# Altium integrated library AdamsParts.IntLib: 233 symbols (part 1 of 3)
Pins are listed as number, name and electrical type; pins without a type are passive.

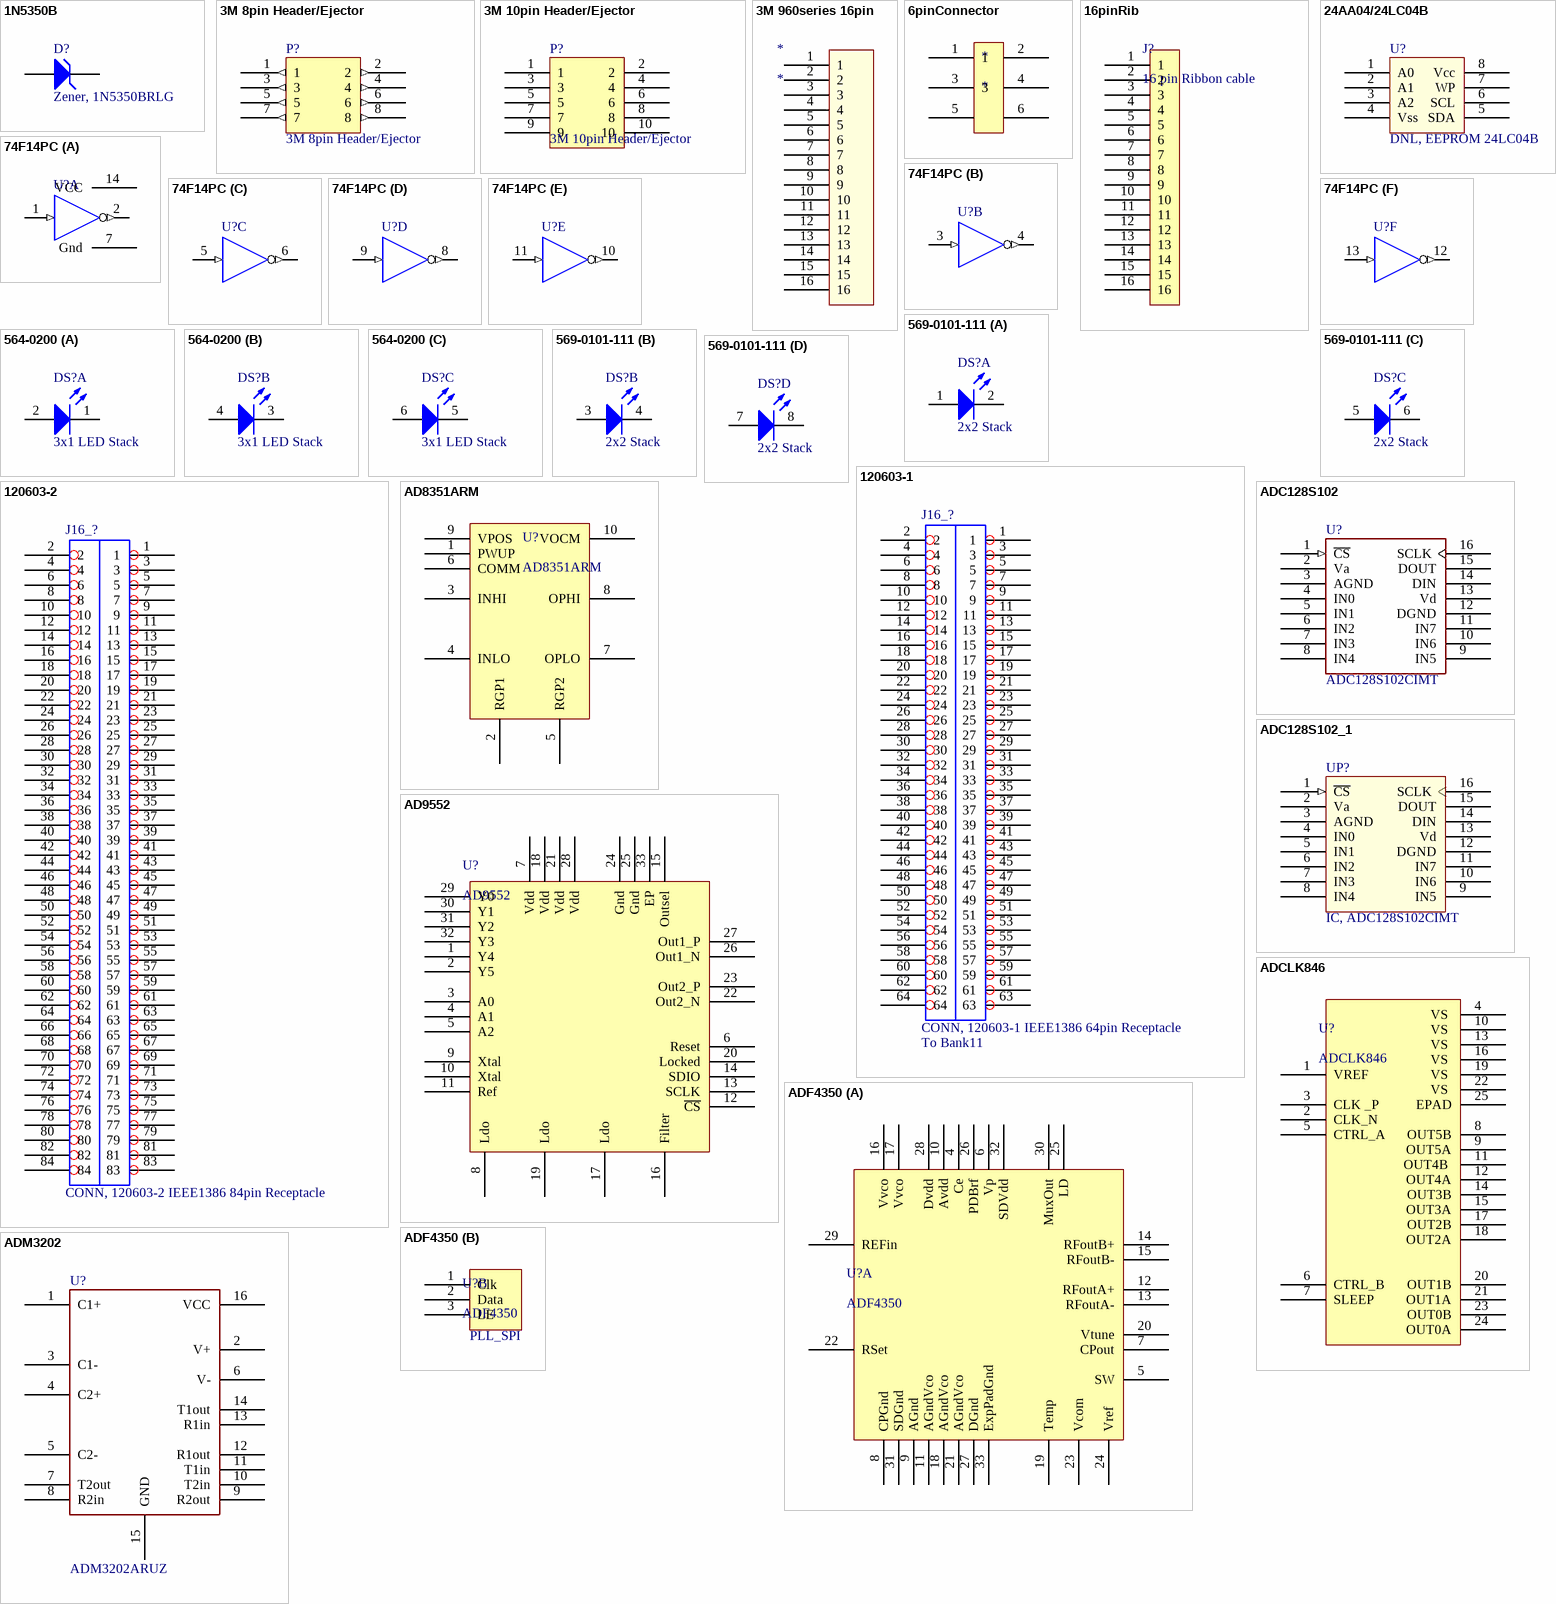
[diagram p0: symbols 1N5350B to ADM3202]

## 1N5350B
designator D?, comment Zener, 1N5350BRLG
Zener Diode, 13V, 5W
footprint A-500 (Diode, Axial; Body 8.9 x 3.7 mm (LxDia. max), Lead Dia. 1.09 mm (max))
simulation model 1N5350B (DIODE)
signal-integrity model 1N5350B
pins: 1 A, 2 K

## 3M 8pin Header/Ejector
designator P?
footprint 3M 8pin latch/ejector
pins: 1 (out), 2 (out), 3 (out), 4 (out), 5 (out), 6 (out), 7 (out), 8 (out)

## 3M 10pin Header/Ejector
designator P?
footprint 3M 10pin latch/ejector
pins: 1, 2, 3, 4, 5, 6, 7, 8, 9, 10

## 3M 960series 16pin
designator *
footprint 3M 960series 16pin
pins: 1, 2, 3, 4, 5, 6, 7, 8, 9, 10, 11, 12, 13, 14, 15, 16

## 6pinConnector
designator *
footprint Tyco 6pin Shrouded Header
pins: 1, 2, 3, 4, 5, 6

## 16pinRib
designator J?, comment 16 pin Ribbon cable
footprint 16pinRib (16 pin ribbon connector)
pins: 1, 2, 3, 4, 5, 6, 7, 8, 9, 10, 11, 12, 13, 14, 15, 16

## 24AA04/24LC04B
designator U?, comment DNL, EEPROM 24LC04B
4K I2C Serial EEPROM
footprint TSSOP8-4.4 (8-Lead Plastic TSSOP 4.4mm)
pins: 1 A0, 2 A1, 3 A2, 4 Vss (power), 5 SDA, 6 SCL, 7 WP, 8 Vcc (power)

## 74F14PC
designator U?
Hex Inverter Schmitt-Trigger, 14-Pin PDIP, Commercial Grade; IC_Technology: F
footprint N14A (DIP, 14-Leads, Row Spacing 7.62mm, Pitch 2.54mm, Body 19.18x6.35mm)
3D model N14A (DIP, 14-Pin, Row Spacing 7.62 mm, Pitch 2.54 mm)
simulation model FSC_74F14 (SIMCODE)
signal-integrity model 74F14PC
part A pins: 1 I (in), 2 ~{O} (out), 7 Gnd, 14 VCC
part B pins: 3 I (in), 4 ~{O} (out)
part C pins: 5 I (in), 6 ~{O} (out)
part D pins: 8 ~{O} (out), 9 I (in)
part E pins: 10 ~{O} (out), 11 I (in)
part F pins: 12 ~{O} (out), 13 I (in)

## 564-0200
designator DS?, comment 3x1 LED Stack
Color: Green (x 3); Configuration: 3 high x 1 wide; Voltage Rating: 2.0V; Current: 20mA; Lens Style/Size: Round, 3mm, T-1; Lens Type: Diffused, Red Tinted
footprint LED3x1
part A pins: 1 K1, 2 A1
part B pins: 3 K2, 4 A2
part C pins: 5 K3, 6 A3

## 569-0101-111
designator DS?, comment 2x2 Stack
LED 2X2 3MM HI DENSITY RED PCMNT; Color: Red (x 4); Configuration: 2 high x 2 wide; Voltage Rating: 2.0V; Current: 20mA; Lens Style/Size: Round, 3mm, T-1; Lens Type: Diffused, Red Tinted
footprint LED2x2 (LED 2x2 Stack from Dialight)
part A pins: 1 A1, 2 K1
part B pins: 3 A2, 4 K2
part C pins: 5 A3, 6 K3
part D pins: 7 A4, 8 K4

## 120603-1
designator J16_?, comment CONN, 120603-1 IEEE1386 64pin Receptacle  Relation: To Bank11
1.0mm FH (IEEE1386) 64-pin Connector
footprint 120603-1
pins: 1, 2, 3, 4, 5, 6, 7, 8, 9, 10, 11, 12, 13, 14, 15, 16, 17, 18, 19, 20, 21, 22, 23, 24, 25, 26, 27, 28, 29, 30, 31, 32, 33, 34, 35, 36, 37, 38, 39, 40, 41, 42, 43, 44, 45, 46, 47, 48, 49, 50, 51, 52, 53, 54, 55, 56, 57, 58, 59, 60, 61, 62, 63, 64

## 120603-2
designator J16_?, comment CONN, 120603-2 IEEE1386 84pin Receptacle
1.0mm FH (IEEE1386) 84-pin Connector
footprint 120603-2 (1.0mm FH (IEEE1386) 84-Pin Connector)
pins: 1, 2, 3, 4, 5, 6, 7, 8, 9, 10, 11, 12, 13, 14, 15, 16, 17, 18, 19, 20, 21, 22, 23, 24, 25, 26, 27, 28, 29, 30, 31, 32, 33, 34, 35, 36, 37, 38, 39, 40, 41, 42, 43, 44, 45, 46, 47, 48, 49, 50, 51, 52, 53, 54, 55, 56, 57, 58, 59, 60, 61, 62, 63, 64, 65, 66, 67, 68, 69, 70, 71, 72, 73, 74, 75, 76, 77, 78, 79, 80, 81, 82, 83, 84

## AD8351ARM
designator U?
footprint MSOP-UN10_N (TSSOP, 10-Leads, Body 3x3mm, Pitch 0.5mm, IPC Medium Density)
pins: 1 PWUP, 2 RGP1, 3 INHI, 4 INLO, 5 RGP2, 6 COMM, 7 OPLO, 8 OPHI, 9 VPOS, 10 VOCM

## AD9552
designator U?
PLL
footprint QFN50P500X475X100-32N (QFN, 32-Leads, Body 4.8x5.0mm (max), Pitch 0.50mm, IPC Medium Density)
pins: 1 Y4, 2 Y5, 3 A0, 4 A1, 5 A2, 6 Reset, 7 Vdd, 8 Ldo, 9 Xtal, 10 Xtal, 11 Ref, 12 ~{CS}, 13 SCLK, 14 SDIO, 15 Outsel, 16 Filter, 17 Ldo, 18 Vdd, 19 Ldo, 20 Locked, 21 Vdd, 22 Out2_N, 23 Out2_P, 24 Gnd, 25 Gnd, 26 Out1_N, 27 Out1_P, 28 Vdd, 29 Y0, 30 Y1, 31 Y2, 32 Y3, 33 EP

## ADC128S102
designator U?, comment ADC128S102CIMT
ADC, 8-Channels, 500kSPS to 1 MSPS, 12-Bit; Manufacturer: National Semiconductor; Manufacturers P/N: ADC128S102CIMT/NOPB
footprint TSSOP-16
pins: 1 ~{CS} (in), 2 Va (power), 3 AGND (power), 4 IN0, 5 IN1, 6 IN2, 7 IN3, 8 IN4, 9 IN5, 10 IN6, 11 IN7, 12 DGND (power), 13 Vd (power), 14 DIN, 15 DOUT, 16 SCLK

## ADC128S102_1
designator UP?, comment IC, ADC128S102CIMT
8-Channels, 500kSPS to 1 MSPS, 12-Bit ADC
footprint SSO-G16/X.45 (SSOP; 16 Leads; Body Width 5.3 mm; Pitch 0.65 mm)
pins: 1 ~{CS} (in), 2 Va (power), 3 AGND (power), 4 IN0, 5 IN1, 6 IN2, 7 IN3, 8 IN4, 9 IN5, 10 IN6, 11 IN7, 12 DGND (power), 13 Vd (power), 14 DIN, 15 DOUT, 16 SCLK

## ADCLK846
designator U?
Clock fanout buffer
footprint QFN50P400X375X100-24N (QFN, 24-Leads, Body 3.8x4.0mm (max), Pitch 0.50mm, IPC Medium Density)
pins: 1 VREF , 2 CLK_N, 3 CLK _P, 4 VS , 5 CTRL_A , 6 CTRL_B , 7 SLEEP , 8 OUT5B, 9 OUT5A, 10 VS , 11 OUT4B , 12 OUT4A, 13 VS , 14 OUT3B, 15 OUT3A, 16 VS , 17 OUT2B, 18 OUT2A, 19 VS , 20 OUT1B, 21 OUT1A, 22 VS , 23 OUT0B, 24 OUT0A, 25 EPAD

## ADF4350
designator U?
footprint QFN50P500X475X100-32M (QFN, 32-Leads, Body 4.8x5.0mm (max), Pitch 0.50mm, IPC Low Density)
part A pins: 4 Ce, 5 SW, 6 Vp, 7 CPout, 8 CPGnd, 9 AGnd, 10 Avdd, 11 AGndVco, 12 RFoutA+, 13 RFoutA-, 14 RFoutB+, 15 RFoutB-, 16 Vvco, 17 Vvco, 18 AGndVco, 19 Temp, 20 Vtune, 21 AGndVco, 22 RSet, 23 Vcom, 24 Vref, 25 LD, 26 PDBrf, 27 DGnd, 28 Dvdd, 29 REFin, 30 MuxOut, 31 SDGnd, 32 SDVdd, 33 ExpPadGnd
part B pins: 1 Clk, 2 Data, 3 LE

## ADM3202
designator U?, comment ADM3202ARUZ
Transceiver, Dual RS232; Manufacturer: Analog Devices Inc
footprint TSSOP-16
pins: 1 C1+, 2 V+ (power), 3 C1-, 4 C2+, 5 C2-, 6 V- (power), 7 T2out, 8 R2in, 9 R2out, 10 T2in, 11 T1in, 12 R1out, 13 R1in, 14 T1out, 15 GND (power), 16 VCC (power)

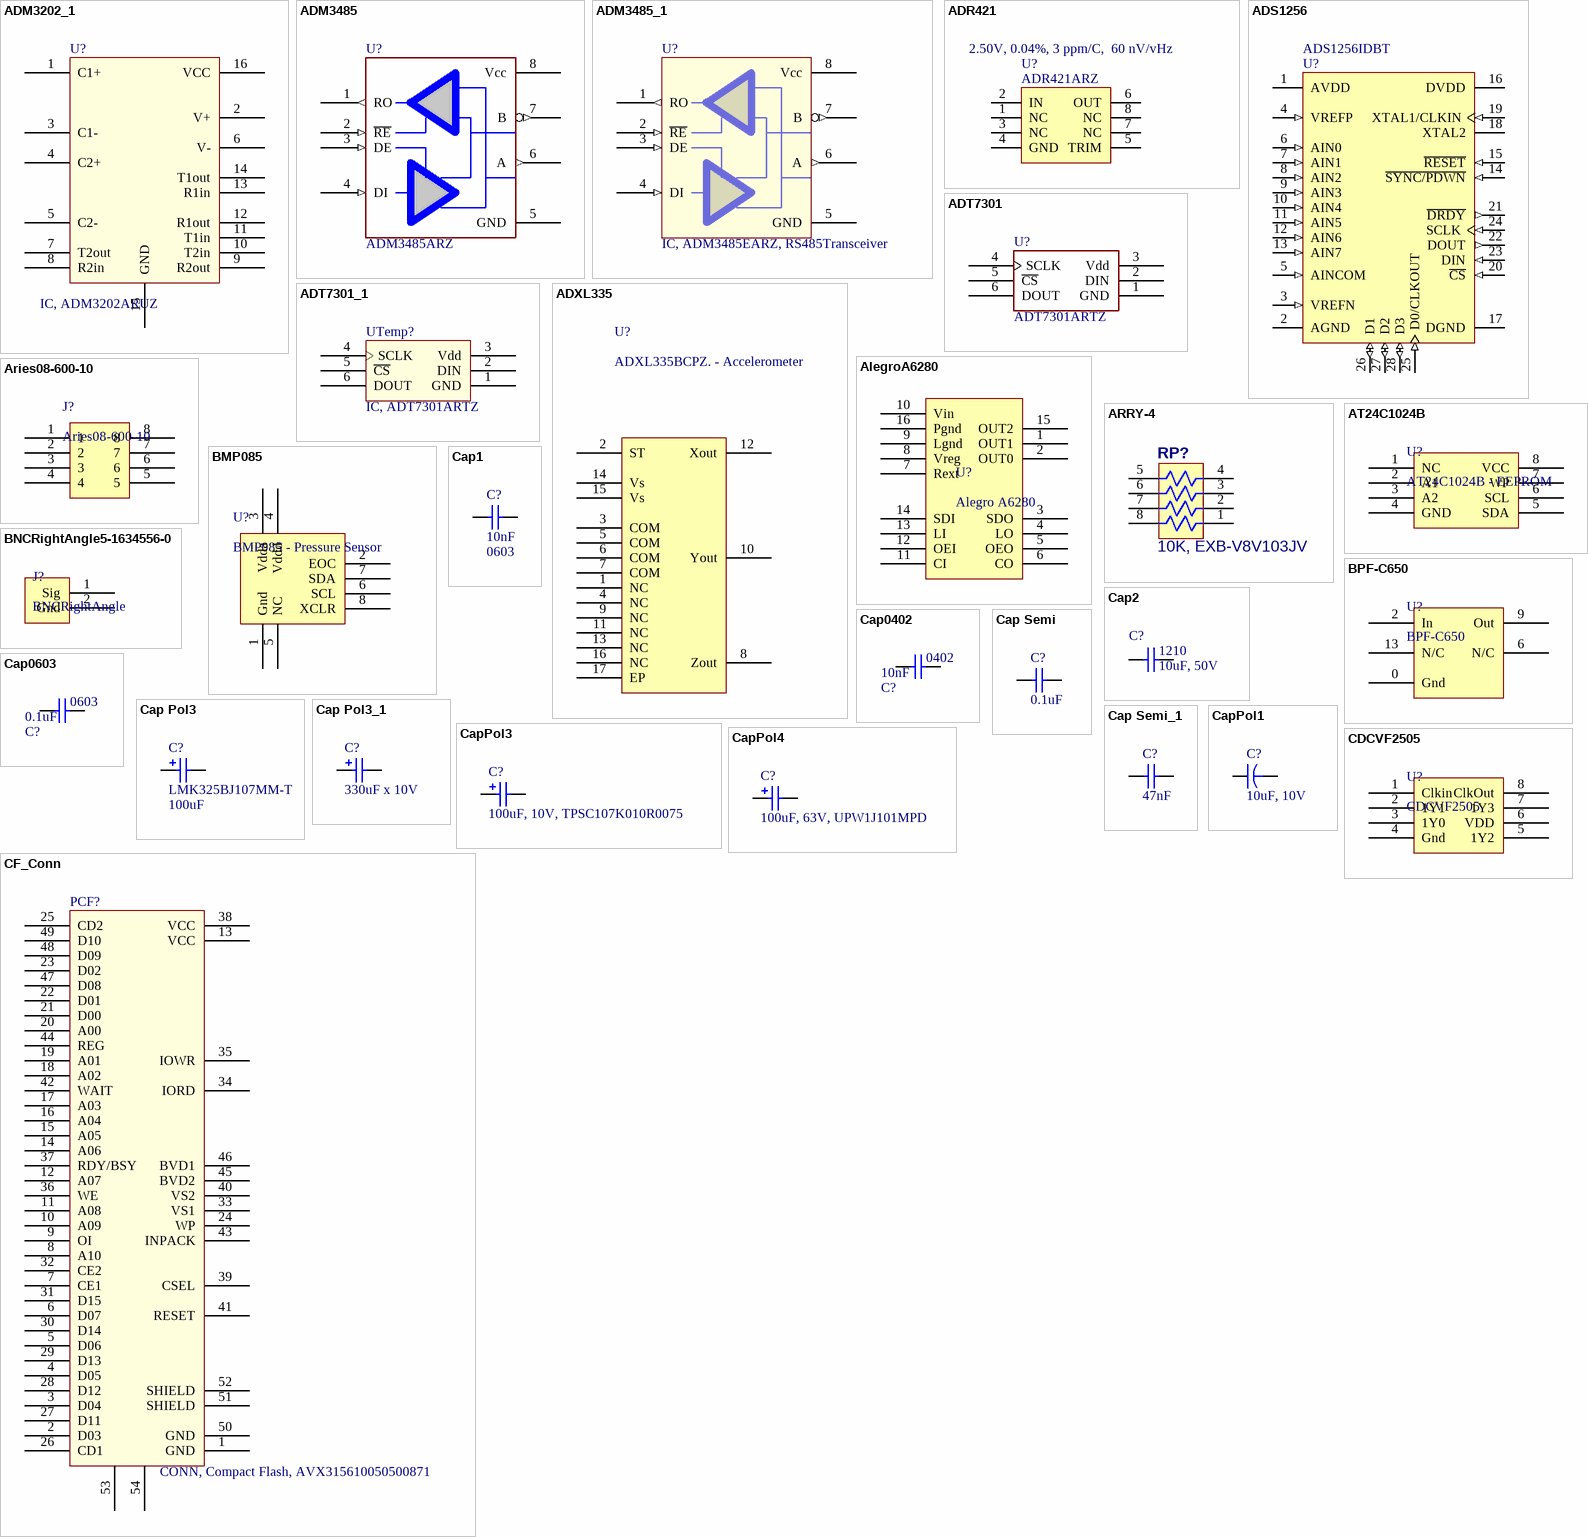
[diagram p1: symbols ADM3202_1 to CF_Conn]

## ADM3202_1
designator U?, comment IC, ADM3202ARUZ
Line Drivers/Receivers
footprint SSO-G16/X.45 (SSOP; 16 Leads; Body Width 5.3 mm; Pitch 0.65 mm)
pins: 1 C1+, 2 V+ (power), 3 C1-, 4 C2+, 5 C2-, 6 V- (power), 7 T2out, 8 R2in, 9 R2out, 10 T2in, 11 T1in, 12 R1out, 13 R1in, 14 T1out, 15 GND (power), 16 VCC (power)

## ADM3485
designator U?, comment ADM3485ARZ
Transceiver, 20 Mbps, EIA RS-485; Manufacturer: Analog Devices Inc
footprint SO8
pins: 1 RO (out), 2 ~{RE} (in), 3 DE (in), 4 DI (in), 5 GND (power), 6 A (out), 7 B (out), 8 Vcc (power)

## ADM3485_1
designator U?, comment IC, ADM3485EARZ, RS485Transceiver
20 Mbps, EIA RS-485 Transceiver
footprint SO-G8/Y1.9 (Small Outline; 8 Leads; Body Width 3.9 mm; Pitch 1.27 mm)
pins: 1 RO (out), 2 ~{RE} (in), 3 DE (in), 4 DI (in), 5 GND (power), 6 A (out), 7 B (out), 8 Vcc (power)

## ADR421
designator U?, comment ADR421ARZ  Param: 2.50V, 0.04%, 3 ppm/C,  60 nV/vHz
Voltage Reference, 2.50V, 0.04%; Manufacturer: Analog Devices Inc
footprint SO8
pins: 1 NC, 2 IN (power), 3 NC, 4 GND (power), 5 TRIM, 6 OUT (power), 7 NC, 8 NC

## ADS1256
designator U?, comment ADS1256IDBT
ADC 24-Bit; Manufacturer: Texas Instruments
footprint SSOP-28
pins: 1 AVDD (power), 2 AGND (power), 3 VREFN (in), 4 VREFP (in), 5 AINCOM (in), 6 AIN0 (in), 7 AIN1 (in), 8 AIN2 (in), 9 AIN3 (in), 10 AIN4 (in), 11 AIN5 (in), 12 AIN6 (in), 13 AIN7 (in), 14 ~{SYNC/PDWN} (in), 15 ~{RESET} (in), 16 DVDD (power), 17 DGND (power), 18 XTAL2, 19 XTAL1/CLKIN (in), 20 ~{CS} (in), 21 ~{DRDY} (out), 22 DOUT (out), 23 DIN (in), 24 SCLK (in), 25 D0/CLKOUT (in), 26 D1 (io), 27 D2 (io), 28 D3 (io)

## ADT7301
designator U?, comment ADT7301ARTZ
Digital Temperature Sensor, 13-Bit, +/-1 Degree Accurate; Manufacturer: Analog Devices Inc
footprint SOT23-6 (SOT-23/SC-74A; 5 Leads; Body 3.1 x 3 mm, inc. leads (LxW max))
pins: 1 GND (power), 2 DIN, 3 Vdd (power), 4 SCLK, 5 ~{CS}, 6 DOUT

## ADT7301_1
designator UTemp?, comment IC, ADT7301ARTZ
Digital Temperature Sensor, 13-Bit, +/-1 Degree Accurate
footprint SO-G6/E2.4 (Small Outline; 6 Leads; Body 3.6 x 3.6 mm, inc. leads (LxW max))
pins: 1 GND (power), 2 DIN, 3 Vdd (power), 4 SCLK, 5 ~{CS}, 6 DOUT

## ADXL335
designator U?, comment ADXL335BCPZ. - Accelerometer
footprint ADXL335 (QFN, 16-Leads, Body 4.2x4.2mm (max), Pitch 0.65mm, IPC Low Density)
pins: 1 NC, 2 ST, 3 COM, 4 NC, 5 COM, 6 COM, 7 COM, 8 Zout, 9 NC, 10 Yout, 11 NC, 12 Xout, 13 NC, 14 Vs, 15 Vs, 16 NC, 17 EP

## AlegroA6280
designator U?, comment Alegro A6280
footprint DIP16
pins: 1 OUT1, 2 OUT0, 3 SDO, 4 LO, 5 OEO, 6 CO, 7 Rext, 8 Vreg, 9 Lgnd, 10 Vin, 11 CI, 12 OEI, 13 LI, 14 SDI, 15 OUT2, 16 Pgnd

## Aries08-600-10
designator J?
Aries08-600-10 - Dip 8 header
footprint Aries08-600-10 (8 PIN DIP HEADER)
pins: 1, 2, 3, 4, 5, 6, 7, 8

## ARRY-4
designator RP?, comment 10K, EXB-V8V103JV
4x 0603 RES ARRAY 10K OHM 5% SMD; Part Field 1: Chip Resistor Array in 3.2 x 1.6 Concave package; Manufacturer: Panasonic - ECG
footprint EXB-V8V
pins: 1 R1A, 2 R2A, 3 R3A, 4 R4A, 5 R4B, 6 R3B, 7 R2B, 8 R1B

## AT24C1024B
designator U?, comment AT24C1024B - EEPROM
footprint SO8/L200
pins: 1 NC, 2 A1, 3 A2, 4 GND, 5 SDA, 6 SCL, 7 WP, 8 VCC

## BMP085
designator U?, comment BMP085 - Pressure Sensor
footprint BMP085 (Pressure sensor)
pins: 1 Gnd, 2 EOC, 3 Vdda, 4 Vddd, 5 NC, 6 SCL, 7 SDA, 8 XCLR

## BNCRightAngle5-1634556-0
designator J?, comment BNCRightAngle
footprint BNCRightAngle5-1634556-0
pins: 1 Sig, 2 Gnd

## BPF-C650
designator U?
footprint HU1186
pins: 0 Gnd, 2 In, 6 N/C, 9 Out, 13 N/C

## Cap1
designator C?, comment 10nF  Footprint: 0603
CAP 10000PF 5% 50V CERAMIC X7R 0603 (or Equivalent); Manufacturer: Kemet; Manufacturers P/N: C0603C103J5RACTU
simulation model CAP (Capacitor)
signal-integrity model Cap
footprint 0603
pins: 1, 2

## Cap2
designator C?, comment 10uF, 50V  Footprint: 1210
CAP CER 10UF, 50V, 10%, UMK325BJ106KM-T; Manufacturer: Taiyo Yuden; Param: 50V, X5R, 10%
simulation model CAP (Capacitor)
signal-integrity model Cap
footprint 1210
pins: 1, 2

## Cap0402
designator C?, comment 10nF  Footprint: 0402
Capacitor, Ceramic, 0402
simulation model CAP (Capacitor)
signal-integrity model Cap
pins: 1, 2

## Cap0603
designator C?, comment 0.1uF  Footprint: 0603
Capacitor, Ceramic, 0603
simulation model CAP (Capacitor)
signal-integrity model Cap
footprint 0603
footprint 0805
pins: 1, 2

## Cap Pol3
designator C?, comment LMK325BJ107MM-T  value 100uF
CAP CER 100UF 10V X5R 1210 20%; Manufacturer: Taiyo Yuden
simulation model CAP (Capacitor)
signal-integrity model Cap Pol
footprint 1210 (Chip Capacitor; Body 3.2 x 2.5 mm (LxW typ))
pins: 1, 2
1 alternate drawing of the same symbol

## Cap Pol3_1
designator C?, comment 330uF x 10V
CAP TANTD TPSD337K010R0100
footprint CC2012-0805 (Chip Capacitor; Body 2.0 x 1.2 mm (LxW typ))
footprint CC4532-1812 (Chip Capacitor; Body 4.5 x 3.2 mm (LxW typ))
footprint CC4564-1825 (Chip Capacitor; Body 4.5 x 6.4 mm (LxW typ))
footprint CC5664-2225 (Chip Capacitor; Body 5.6 x 6.4 mm (LxW typ))
footprint CC5750-2220 (Chip Capacitor; Body 5.7 x 5.0 mm (LxW typ))
simulation model CAP (Capacitor)
signal-integrity model Cap Pol
footprint CC7343-31_Dsize
pins: 1, 2
1 alternate drawing of the same symbol

## Cap Semi
designator C?, comment 0.1uF
CAP .10UF 5% 16V CERAMIC X7R 0603 (or Equivalent); Manufacturer: Kemet; Manufacturers P/N: C0603C104J4RACTU
footprint CC3216-1206 (Chip Capacitor; Body 3.2 x 1.6 mm (LxW typ))
footprint CC1005-0402 (Chip Capacitor; Body 1.0 x 0.5 mm (LxW typ))
footprint CC1310-0504 (Chip Capacitor; Body 1.2 x 1.0 mm (LxW typ))
footprint CC1608-0603 (Chip Capacitor; Body 1.6 x 0.8 mm (LxW typ))
footprint CC3225-1210 (Chip Capacitor; Body 3.2 x 2.5 mm (LxW typ))
simulation model CAP (Semiconductor Capacitor)
signal-integrity model Cap Semi
pins: 1, 2

## Cap Semi_1
designator C?, comment 47nF
Capacitor (Semiconductor SIM Model)
footprint CC3216-1206 (Chip Capacitor; Body 3.2 x 1.6 mm (LxW typ))
footprint CC1005-0402 (Chip Capacitor; Body 1.0 x 0.5 mm (LxW typ))
footprint CC1310-0504 (Chip Capacitor; Body 1.2 x 1.0 mm (LxW typ))
footprint CC1608-0603 (Chip Capacitor; Body 1.6 x 0.8 mm (LxW typ))
footprint CC3225-1210 (Chip Capacitor; Body 3.2 x 2.5 mm (LxW typ))
simulation model CAP (Semiconductor Capacitor)
signal-integrity model Cap Semi
pins: 1, 2

## CapPol1
designator C?, comment 10uF, 10V
CAP CER 10V, X5R, 10%, LMK212BJ106KG-T; Manufacturer: Taiyo Yuden
simulation model CAP (Capacitor)
signal-integrity model Cap
footprint 0805
pins: 1, 2

## CapPol3
designator C?, comment 100uF, 10V, TPSC107K010R0075
CAP TANT LOESR 100uFx10V 10% SMD; Manufacturer: AVX Corporation
simulation model CAP (Capacitor)
signal-integrity model Cap Pol
footprint TCASE-D
pins: 1, 2
1 alternate drawing of the same symbol

## CapPol4
designator C?, comment 100uF, 63V, UPW1J101MPD
CAP Radial 100uF 63V 20% (or Equivalent); Manufacturer: Nichicon
simulation model CAP (Capacitor)
signal-integrity model Cap Pol
footprint CC-10X12-5
pins: 1, 2
1 alternate drawing of the same symbol

## CDCVF2505
designator U?
PLL 24->200Mhz PLL
footprint TSOP65P640X120-8N (TSOP, 8-Leads, Body 3.1x4.5mm (max), Pitch 0.65mm, IPC Medium Density)
footprint SO8
pins: 1 Clkin, 2 1Y1, 3 1Y0, 4 Gnd, 5 1Y2, 6 VDD, 7 1Y3, 8 ClkOut

## CF_Conn
designator PCF?, comment CONN, Compact Flash, AVX315610050500871
Compact Flash Connector
footprint CF/SM0.635-6H50 (Connector; CompactFlash Card Header, SM; Normal Polarization; 50 Position; Right Angle; Pitch 0.635 mm)
footprint CF_AVX5611 (CompactFlash Card Header, SM; Normal Polarization; 50 Position; Right Angle; Pitch 0.635 mm)
pins: 1 GND, 2 D03, 3 D04, 4 D05, 5 D06, 6 D07, 7 CE1, 8 A10, 9 OI, 10 A09, 11 A08, 12 A07, 13 VCC, 14 A06, 15 A05, 16 A04, 17 A03, 18 A02, 19 A01, 20 A00, 21 D00, 22 D01, 23 D02, 24 WP, 25 CD2, 26 CD1, 27 D11, 28 D12, 29 D13, 30 D14, 31 D15, 32 CE2, 33 VS1, 34 IORD, 35 IOWR, 36 WE, 37 RDY/BSY, 38 VCC, 39 CSEL, 40 VS2, 41 RESET, 42 WAIT, 43 INPACK, 44 REG, 45 BVD2, 46 BVD1, 47 D08, 48 D09, 49 D10, 50 GND, 51 SHIELD, 52 SHIELD, 53 GND, 54 GND

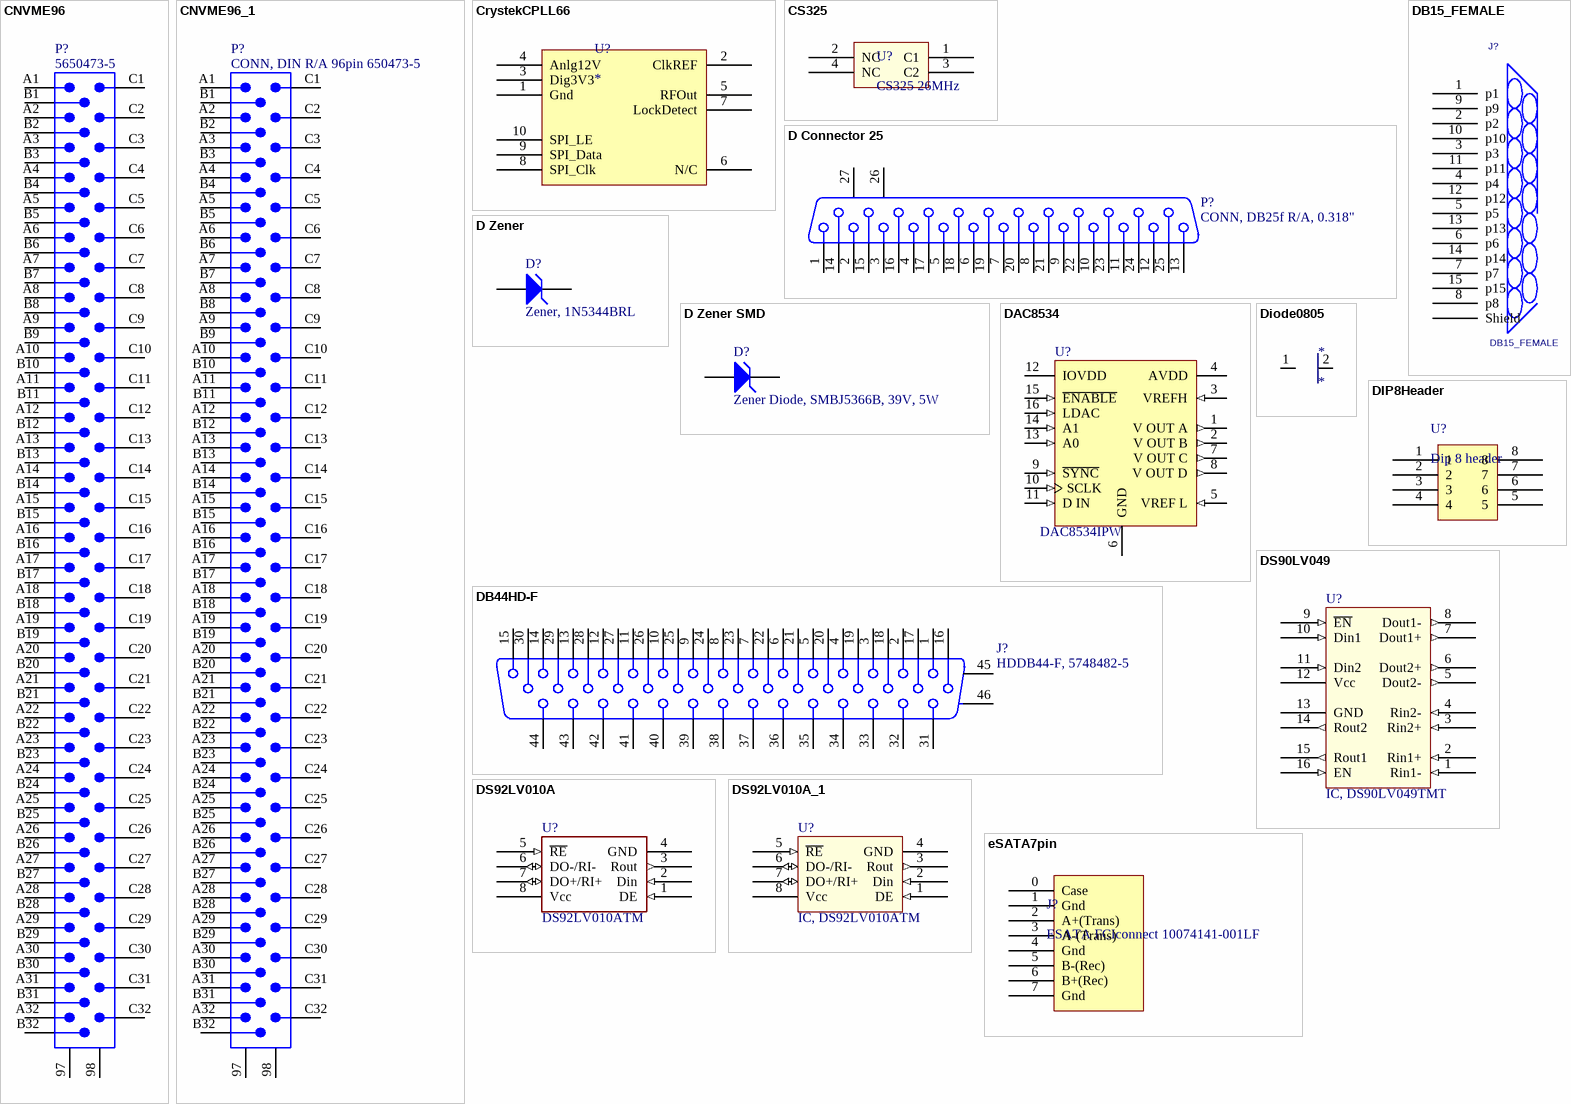
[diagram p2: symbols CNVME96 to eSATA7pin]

## CNVME96
designator P?, comment 5650473-5
CONN, EURO 96-Pin (3x32 2.54mm grid); Manufacturer: Tyco Electronics; Text Field6: Alternate Layout Available; Text Field7: Published 14-Feb-2002
footprint CNVME96
pins: 97, 98, A1, A2, A3, A4, A5, A6, A7, A8, A9, A10, A11, A12, A13, A14, A15, A16, A17, A18, A19, A20, A21, A22, A23, A24, A25, A26, A27, A28, A29, A30, A31, A32, B1, B2, B3, B4, B5, B6, B7, B8, B9, B10, B11, B12, B13, B14, B15, B16, B17, B18, B19, B20, B21, B22, B23, B24, B25, B26, B27, B28, B29, B30, B31, B32, C1, C2, C3, C4, C5, C6, C7, C8, C9, C10, C11, C12, C13, C14, C15, C16, C17, C18, C19, C20, C21, C22, C23, C24, C25, C26, C27, C28, C29, C30, C31, C32
1 alternate drawing of the same symbol

## CNVME96_1
designator P?, comment CONN, DIN R/A 96pin 650473-5
96-Pin Connector (3x32 2.54mm grid); Text Field6: Alternate Layout Available; Text Field7: Published 14-Feb-2002
footprint CNVME96
pins: 97, 98, A1, A2, A3, A4, A5, A6, A7, A8, A9, A10, A11, A12, A13, A14, A15, A16, A17, A18, A19, A20, A21, A22, A23, A24, A25, A26, A27, A28, A29, A30, A31, A32, B1, B2, B3, B4, B5, B6, B7, B8, B9, B10, B11, B12, B13, B14, B15, B16, B17, B18, B19, B20, B21, B22, B23, B24, B25, B26, B27, B28, B29, B30, B31, B32, C1, C2, C3, C4, C5, C6, C7, C8, C9, C10, C11, C12, C13, C14, C15, C16, C17, C18, C19, C20, C21, C22, C23, C24, C25, C26, C27, C28, C29, C30, C31, C32
1 alternate drawing of the same symbol

## CrystekCPLL66
designator U?
footprint CPLL66
pins: 1 Gnd, 2 ClkREF, 3 Dig3V3, 4 Anlg12V, 5 RFOut, 6 N/C, 7 LockDetect, 8 SPI_Clk, 9 SPI_Data, 10 SPI_LE

## CS325
designator U?, comment CS325 26MHz
pins: 1 C1, 2 NC, 3 C2, 4 NC

## D Connector 25
designator P?, comment CONN, DB25f R/A, 0.318"
Amp 5747846-4 or ITT DBMG25SJA197; PackageDocument: U; Positions: 25; Gender: Receptacle
footprint DSUB1.385-2H25A (Connector; D Subminiature; 25 Position; Right Angle; Pitch 1.385 mm)
signal-integrity model Connector
pins: 1, 2, 3, 4, 5, 6, 7, 8, 9, 10, 11, 12, 13, 14, 15, 16, 17, 18, 19, 20, 21, 22, 23, 24, 25, 26 MH1, 27 MH2

## D Zener
designator D?, comment Zener, 1N5344BRL
Zener Diode, 8.2V, 5W
footprint DIODE-0.7 (Zener Diode; 2 Leads)
simulation model ZENER (Diode)
signal-integrity model D Zener
pins: 1 A, 2 K

## D Zener SMD
designator D?, comment Zener Diode, SMBJ5366B, 39V, 5W
Zener Diode SMD, 39V, 5W; Manufacturer: Micro Commercial Co; Manufacturers P/N: SMBJ5366B-TP
footprint DO-214AA
pins: 1 K, 2 A

## DAC8534
designator U?, comment DAC8534IPW
DAC, 16-Bit Quad channel, 16-bit, Serial Input; Manufacturer: Texas Instruments
footprint TSSOP-16
pins: 1 V OUT A (out), 2 V OUT B (out), 3 VREFH (in), 4 AVDD (power), 5 VREF L (in), 6 GND (power), 7 V OUT C (out), 8 V OUT D (out), 9 ~{SYNC} (in), 10 SCLK (in), 11 D IN (in), 12 IOVDD (power), 13 A0 (in), 14 A1 (in), 15 ~{ENABLE} (in), 16 LDAC (in)

## DB15_FEMALE
designator J?
COMPFIXED: NO; COMPGROUP: 0; COMPHEIGHT: 0.000; COMPLOC: [4502.733,1338.467]; COMPROT: 270; COMPSIDE: TOP
footprint DSUB/RS.318/TM/15
pins: 1 p1, 2 p2, 3 p3, 4 p4, 5 p5, 6 p6, 7 p7, 8 p8, 9 p9, 10 p10, 11 p11, 12 p12, 13 p13, 14 p14, 15 p15, Hole30 Shield

## DB44HD-F
designator J?, comment HDDB44-F, 5748482-5
CONN, High Density DB44 Female; Manufacturer: Tyco Electronics
footprint DSUBHD44
pins: 1, 2, 3, 4, 5, 6, 7, 8, 9, 10, 11, 12, 13, 14, 15, 16, 17, 18, 19, 20, 21, 22, 23, 24, 25, 26, 27, 28, 29, 30, 31, 32, 33, 34, 35, 36, 37, 38, 39, 40, 41, 42, 43, 44, 45, 46

## Diode0805
designator *
footprint Diode0805
pins: 1, 2

## DIP8Header
designator U?, comment Dip 8 header
footprint DIP8Header (8 PIN DIP HEADER)
pins: 1, 2, 3, 4, 5, 6, 7, 8

## DS90LV049
designator U?, comment IC, DS90LV049TMT
3V LVDS Dual Line Transceiver
footprint TSSO5x6-G16 (Shrink Small Outline; 16 Leads; Body Width 4.4 mm; Pitch 0.65 mm)
pins: 1 Rin1- (in), 2 Rin1+ (in), 3 Rin2+ (in), 4 Rin2- (in), 5 Dout2- (out), 6 Dout2+ (out), 7 Dout1+ (out), 8 Dout1- (out), 9 ~{EN} (in), 10 Din1 (in), 11 Din2 (in), 12 Vcc (power), 13 GND (power), 14 Rout2 (out), 15 Rout1 (out), 16 EN (in)

## DS92LV010A
designator U?, comment DS92LV010ATM
Transceiver, Bus LVDS 3.3/5.0V Single; Manufacturer: National Semiconductor; Manufacturers P/N: DS92LV010ATM/NOPB
footprint SO8
pins: 1 DE (in), 2 Din (in), 3 Rout (out), 4 GND (power), 5 ~{RE} (in), 6 DO-/RI- (io), 7 DO+/RI+ (io), 8 Vcc (power)

## DS92LV010A_1
designator U?, comment IC, DS92LV010ATM
Bus LVDS 3.3/5.0V Single Transceiver
footprint SOP8 (Small Outline; 8 Leads; Body Width 4.3 mm; Pitch 1.27 mm)
pins: 1 DE (in), 2 Din (in), 3 Rout (out), 4 GND (power), 5 ~{RE} (in), 6 DO-/RI- (io), 7 DO+/RI+ (io), 8 Vcc (power)

## eSATA7pin
designator J?, comment ESATA FCIconnect 10074141-001LF
Esata connector FCIconnect 10074141-001LF
footprint ESATA-PU-07 (eSATA connector FCIconnect 10074141-001LF)
pins: 0 Case, 1 Gnd, 2 A+(Trans), 3 A-(Trans), 4 Gnd, 5 B-(Rec), 6 B+(Rec), 7 Gnd

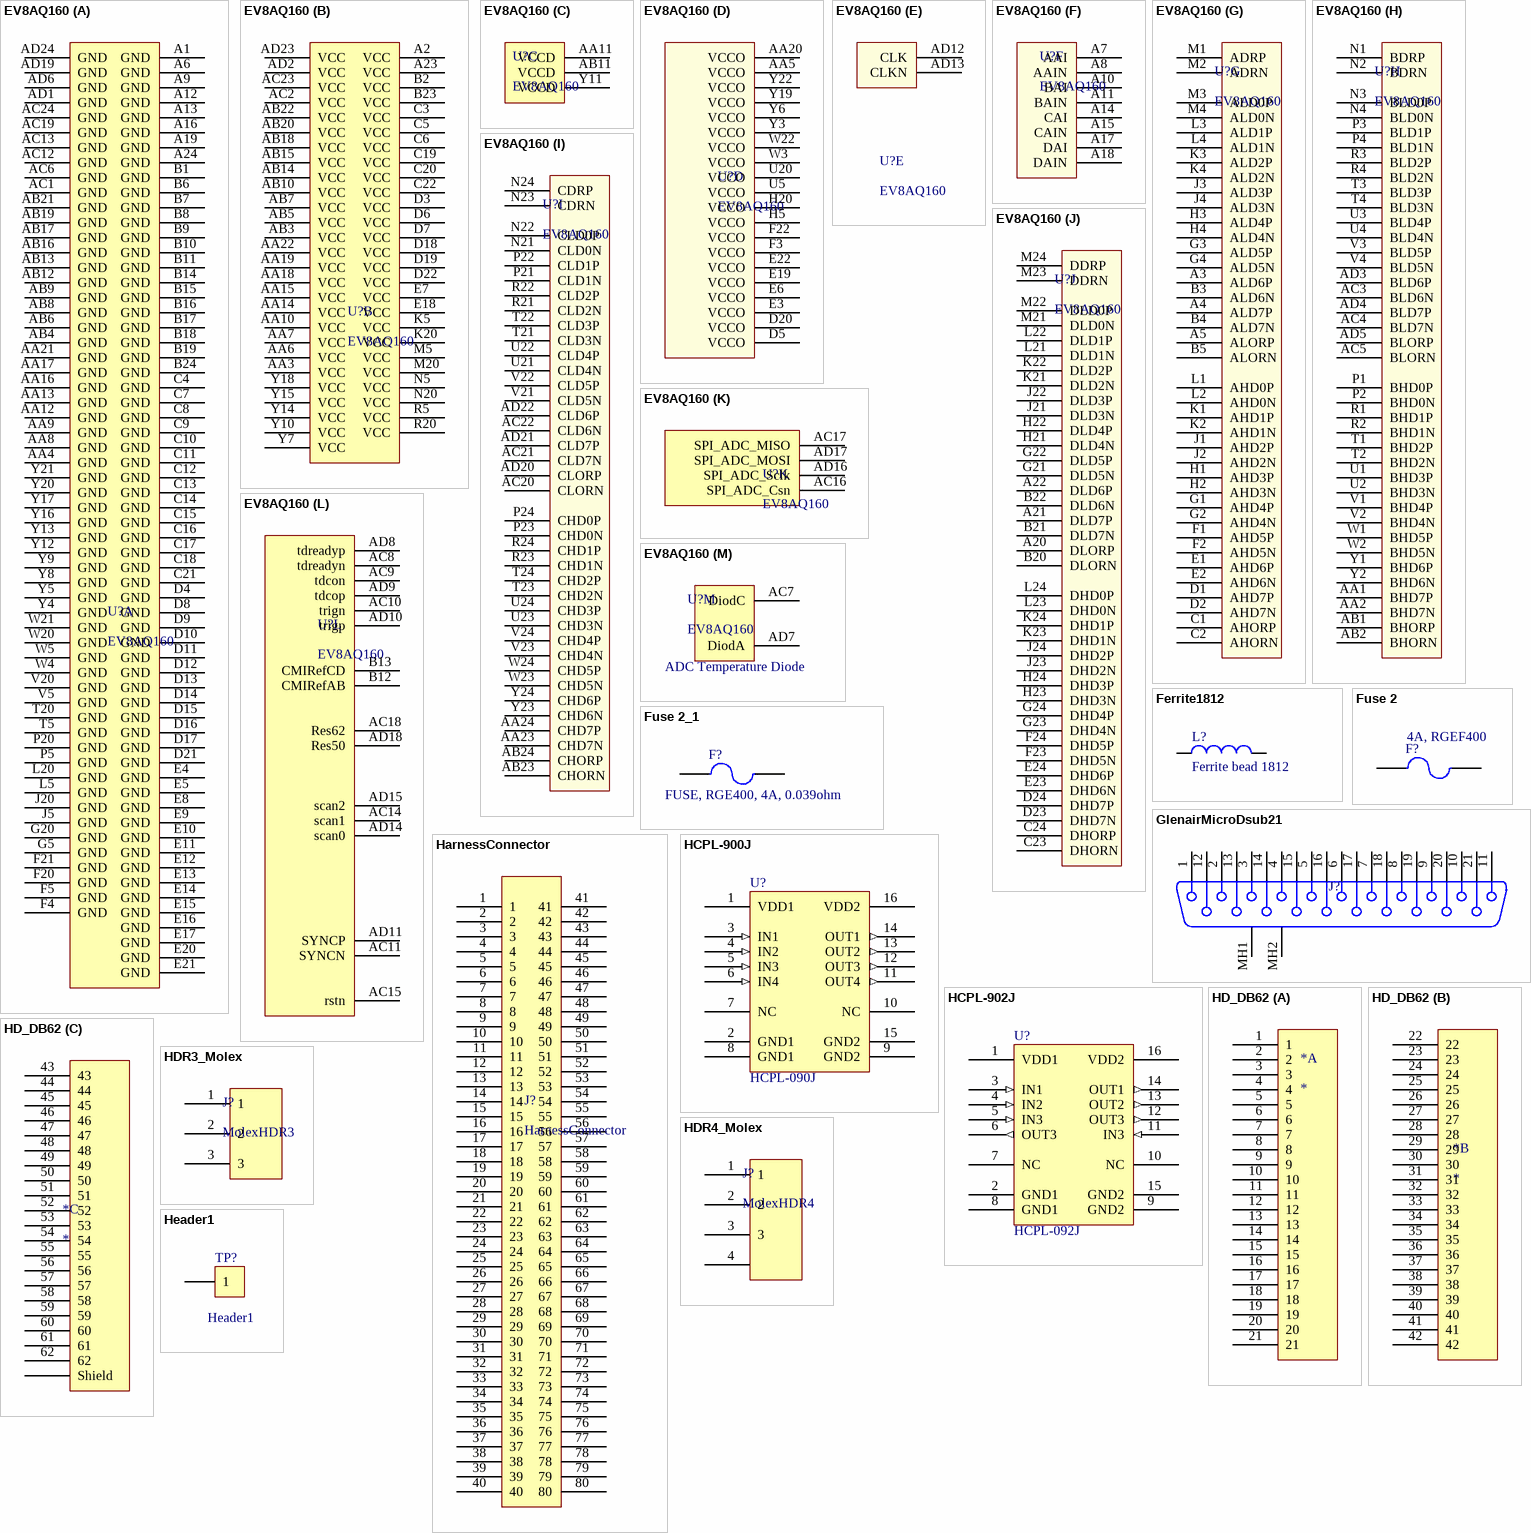
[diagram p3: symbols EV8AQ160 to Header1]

## EV8AQ160
designator U?
footprint BGA380C127P24X24_3100X3100X160 (BGA, 380-Leads, Body 31.0x31.0mm,  Pitch 1.27mm)
part A pins: A1 GND, A6 GND, A9 GND, A12 GND, A13 GND, A16 GND, A19 GND, A24 GND, AA4 GND, AA8 GND, AA9 GND, AA12 GND, AA13 GND, AA16 GND, AA17 GND, AA21 GND, AB4 GND, AB6 GND, AB8 GND, AB9 GND, AB12 GND, AB13 GND, AB16 GND, AB17 GND, AB19 GND, AB21 GND, AC1 GND, AC6 GND, AC12 GND, AC13 GND, AC19 GND, AC24 GND, AD1 GND, AD6 GND, AD19 GND, AD24 GND, B1 GND, B6 GND, B7 GND, B8 GND, B9 GND, B10 GND, B11 GND, B14 GND, B15 GND, B16 GND, B17 GND, B18 GND, B19 GND, B24 GND, C4 GND, C7 GND, C8 GND, C9 GND, C10 GND, C11 GND, C12 GND, C13 GND, C14 GND, C15 GND, C16 GND, C17 GND, C18 GND, C21 GND, D4 GND, D8 GND, D9 GND, D10 GND, D11 GND, D12 GND, D13 GND, D14 GND, D15 GND, D16 GND, D17 GND, D21 GND, E4 GND, E5 GND, E8 GND, E9 GND, E10 GND, E11 GND, E12 GND, E13 GND, E14 GND, E15 GND, E16 GND, E17 GND, E20 GND, E21 GND, F4 GND, F5 GND, F20 GND, F21 GND, G5 GND, G20 GND, J5 GND, J20 GND, L5 GND, L20 GND, P5 GND, P20 GND, T5 GND, T20 GND, V5 GND, V20 GND, W4 GND, W5 GND, W20 GND, W21 GND, Y4 GND, Y5 GND, Y8 GND, Y9 GND, Y12 GND, Y13 GND, Y16 GND, Y17 GND, Y20 GND, Y21 GND
part B pins: A2 VCC, A23 VCC, AA3 VCC, AA6 VCC, AA7 VCC, AA10 VCC, AA14 VCC, AA15 VCC, AA18 VCC, AA19 VCC, AA22 VCC, AB3 VCC, AB5 VCC, AB7 VCC, AB10 VCC, AB14 VCC, AB15 VCC, AB18 VCC, AB20 VCC, AB22 VCC, AC2 VCC, AC23 VCC, AD2 VCC, AD23 VCC, B2 VCC, B23 VCC, C3 VCC, C5 VCC, C6 VCC, C19 VCC, C20 VCC, C22 VCC, D3 VCC, D6 VCC, D7 VCC, D18 VCC, D19 VCC, D22 VCC, E7 VCC, E18 VCC, K5 VCC, K20 VCC, M5 VCC, M20 VCC, N5 VCC, N20 VCC, R5 VCC, R20 VCC, Y7 VCC, Y10 VCC, Y14 VCC, Y15 VCC, Y18 VCC
part C pins: AA11 VCCD, AB11 VCCD, Y11 VCCD
part D pins: AA5 VCCO, AA20 VCCO, D5 VCCO, D20 VCCO, E3 VCCO, E6 VCCO, E19 VCCO, E22 VCCO, F3 VCCO, F22 VCCO, H5 VCCO, H20 VCCO, U5 VCCO, U20 VCCO, W3 VCCO, W22 VCCO, Y3 VCCO, Y6 VCCO, Y19 VCCO, Y22 VCCO
part E pins: AD12 CLK, AD13 CLKN
part F pins: A7 AAI, A8 AAIN, A10 BAI, A11 BAIN, A14 CAI, A15 CAIN, A17 DAI, A18 DAIN
part G pins: A3 ALD6P, A4 ALD7P, A5 ALORP, B3 ALD6N, B4 ALD7N, B5 ALORN, C1 AHORP, C2 AHORN, D1 AHD7P, D2 AHD7N, E1 AHD6P, E2 AHD6N, F1 AHD5P, F2 AHD5N, G1 AHD4P, G2 AHD4N, G3 ALD5P, G4 ALD5N, H1 AHD3P, H2 AHD3N, H3 ALD4P, H4 ALD4N, J1 AHD2P, J2 AHD2N, J3 ALD3P, J4 ALD3N, K1 AHD1P, K2 AHD1N, K3 ALD2P, K4 ALD2N, L1 AHD0P, L2 AHD0N, L3 ALD1P, L4 ALD1N, M1 ADRP, M2 ADRN, M3 ALD0P, M4 ALD0N
part H pins: AA1 BHD7P, AA2 BHD7N, AB1 BHORP, AB2 BHORN, AC3 BLD6N, AC4 BLD7N, AC5 BLORN, AD3 BLD6P, AD4 BLD7P, AD5 BLORP, N1 BDRP, N2 BDRN, N3 BLD0P, N4 BLD0N, P1 BHD0P, P2 BHD0N, P3 BLD1P, P4 BLD1N, R1 BHD1P, R2 BHD1N, R3 BLD2P, R4 BLD2N, T1 BHD2P, T2 BHD2N, T3 BLD3P, T4 BLD3N, U1 BHD3P, U2 BHD3N, U3 BLD4P, U4 BLD4N, V1 BHD4P, V2 BHD4N, V3 BLD5P, V4 BLD5N, W1 BHD5P, W2 BHD5N, Y1 BHD6P, Y2 BHD6N
part I pins: AA23 CHD7N, AA24 CHD7P, AB23 CHORN, AB24 CHORP, AC20 CLORN, AC21 CLD7N, AC22 CLD6N, AD20 CLORP, AD21 CLD7P, AD22 CLD6P, N21 CLD0N, N22 CLD0P, N23 CDRN, N24 CDRP, P21 CLD1N, P22 CLD1P, P23 CHD0N, P24 CHD0P, R21 CLD2N, R22 CLD2P, R23 CHD1N, R24 CHD1P, T21 CLD3N, T22 CLD3P, T23 CHD2N, T24 CHD2P, U21 CLD4N, U22 CLD4P, U23 CHD3N, U24 CHD3P, V21 CLD5N, V22 CLD5P, V23 CHD4N, V24 CHD4P, W23 CHD5N, W24 CHD5P, Y23 CHD6N, Y24 CHD6P
part J pins: A20 DLORP, A21 DLD7P, A22 DLD6P, B20 DLORN, B21 DLD7N, B22 DLD6N, C23 DHORN, C24 DHORP, D23 DHD7N, D24 DHD7P, E23 DHD6N, E24 DHD6P, F23 DHD5N, F24 DHD5P, G21 DLD5N, G22 DLD5P, G23 DHD4N, G24 DHD4P, H21 DLD4N, H22 DLD4P, H23 DHD3N, H24 DHD3P, J21 DLD3N, J22 DLD3P, J23 DHD2N, J24 DHD2P, K21 DLD2N, K22 DLD2P, K23 DHD1N, K24 DHD1P, L21 DLD1N, L22 DLD1P, L23 DHD0N, L24 DHD0P, M21 DLD0N, M22 DLD0P, M23 DDRN, M24 DDRP
part K pins: AC16 SPI_ADC_Csn, AC17 SPI_ADC_MISO, AD16 SPI_ADC_Sclk, AD17 SPI_ADC_MOSI
part L pins: AC8 tdreadyn, AC9 tdcon, AC10 trign, AC11 SYNCN, AC14 scan1, AC15 rstn, AC18 Res62, AD8 tdreadyp, AD9 tdcop, AD10 trigp, AD11 SYNCP, AD14 scan0, AD15 scan2, AD18 Res50, B12 CMIRefAB, B13 CMIRefCD
part M pins: AC7 DiodC, AD7 DiodA

## Ferrite1812
designator L?, comment Ferrite bead 1812
Inductor SM; Code_IEC: 1005
footprint 1812or4532
pins: 1, 2

## Fuse 2
designator F?, comment 4A, RGEF400
FUSE, 4A, 0.039ohm; Manufacturer: Tyco Electronics
simulation model FUSE (Spice Subcircuit)
footprint Fuse GF400
pins: 1, 2

## Fuse 2_1
designator F?, comment FUSE, RGE400, 4A, 0.039ohm
Fuse
footprint PIN-W2/E2.8 (Fuse; 2 Leads)
simulation model FUSE (Spice Subcircuit)
footprint Fuse 5.88mm
pins: 1, 2

## GlenairMicroDsub21
designator J?
GlenairMicroDsub21
signal-integrity model D Subminiature
footprint MicroD21Glenair (Glenair MicroD 21 pin)
pins: 1, 2, 3, 4, 5, 6, 7, 8, 9, 10, 11, 12, 13, 14, 15, 16, 17, 18, 19, 20, 21, MH1, MH2

## HarnessConnector
designator J?
footprint HarnessConnector
pins: 1, 2, 3, 4, 5, 6, 7, 8, 9, 10, 11, 12, 13, 14, 15, 16, 17, 18, 19, 20, 21, 22, 23, 24, 25, 26, 27, 28, 29, 30, 31, 32, 33, 34, 35, 36, 37, 38, 39, 40, 41, 42, 43, 44, 45, 46, 47, 48, 49, 50, 51, 52, 53, 54, 55, 56, 57, 58, 59, 60, 61, 62, 63, 64, 65, 66, 67, 68, 69, 70, 71, 72, 73, 74, 75, 76, 77, 78, 79, 80

## HCPL-900J
designator U?, comment HCPL-090J
Galvanic optoisolator, 4/0 SO16 NARROWBODY; Manufacturer: Avago Technologies US Inc.
footprint SO16
pins: 1 VDD1 (power), 2 GND1 (power), 3 IN1 (in), 4 IN2 (in), 5 IN3 (in), 6 IN4 (in), 7 NC, 8 GND1 (power), 9 GND2 (power), 10 NC, 11 OUT4 (out), 12 OUT3 (out), 13 OUT2 (out), 14 OUT1 (out), 15 GND2 (power), 16 VDD2 (power)

## HCPL-902J
designator U?, comment HCPL-092J
Galvanic optoisolator, 3/1 SO16 NARROWBODY; Manufacturer: Unknown
footprint SO16
pins: 1 VDD1 (power), 2 GND1 (power), 3 IN1 (in), 4 IN2 (in), 5 IN3 (in), 6 OUT3 (out), 7 NC, 8 GND1 (power), 9 GND2 (power), 10 NC, 11 IN3 (in), 12 OUT3 (out), 13 OUT2 (out), 14 OUT1 (out), 15 GND2 (power), 16 VDD2 (power)

## HD_DB62
designator *
footprint HD_DB62
part A pins: 1, 2, 3, 4, 5, 6, 7, 8, 9, 10, 11, 12, 13, 14, 15, 16, 17, 18, 19, 20, 21
part B pins: 22, 23, 24, 25, 26, 27, 28, 29, 30, 31, 32, 33, 34, 35, 36, 37, 38, 39, 40, 41, 42
part C pins: 43, 44, 45, 46, 47, 48, 49, 50, 51, 52, 53, 54, 55, 56, 57, 58, 59, 60, 61, 62, HOLE63 Shield

## HDR3_Molex
designator J?, comment MolexHDR3
footprint HDR1X3_MolexVertical
footprint HDR1X3_MolexRightAngle
pins: 1, 2, 3

## HDR4_Molex
designator J?, comment MolexHDR4
footprint HDR1X4_MolexRightAngle
pins: 1, 2, 3, 4

## Header1
designator TP?
TestPoint1
footprint HDR1
pins: 1

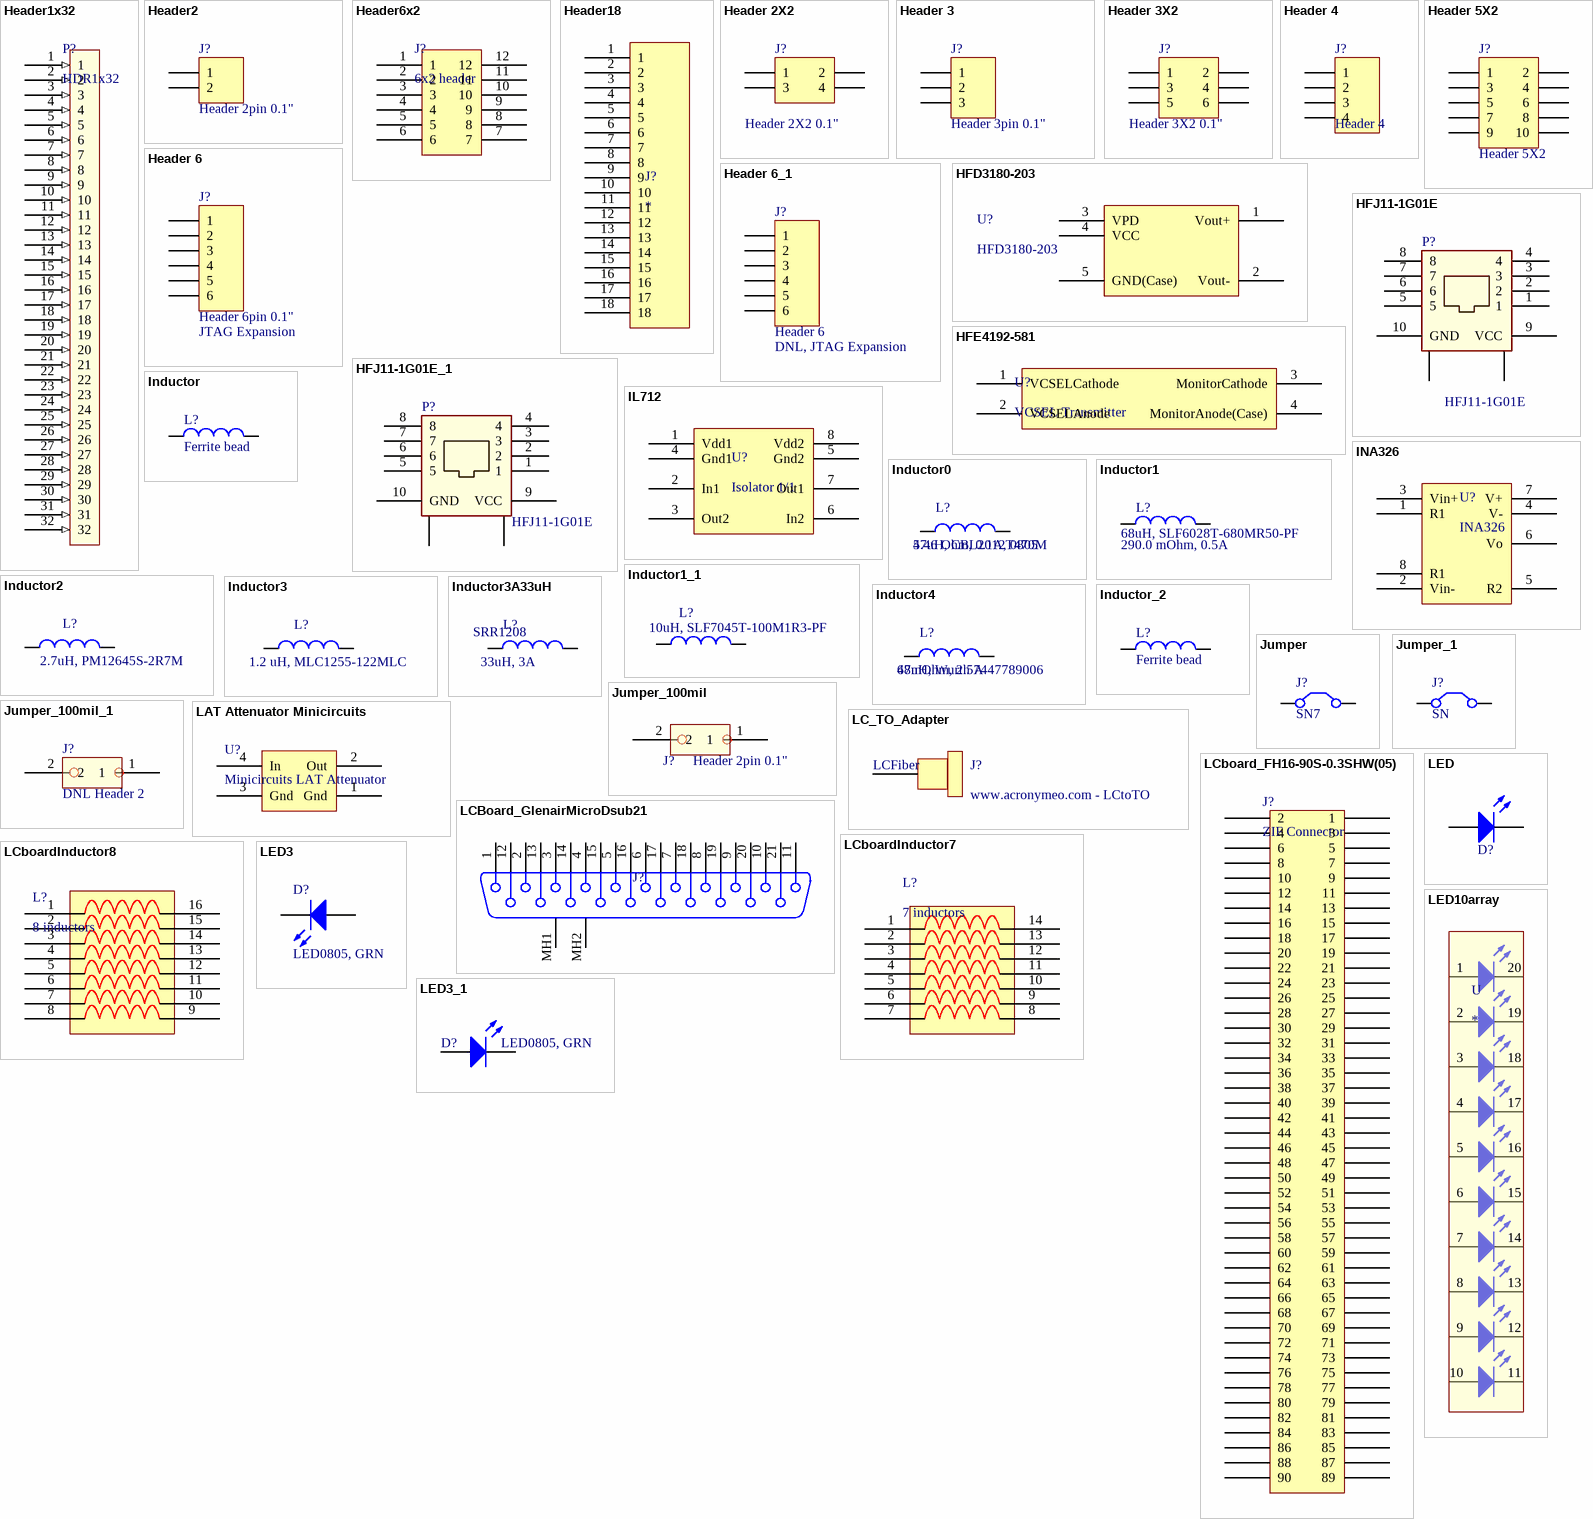
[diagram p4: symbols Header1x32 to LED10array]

## Header1x32
designator P?, comment HDR1x32
footprint Header1x32
pins: 1 (in), 2 (in), 3 (in), 4 (in), 5 (in), 6 (in), 7 (in), 8 (in), 9 (in), 10 (in), 11 (in), 12 (in), 13 (in), 14 (in), 15 (in), 16 (in), 17 (in), 18 (in), 19 (in), 20 (in), 21 (in), 22 (in), 23 (in), 24 (in), 25 (in), 26 (in), 27 (in), 28 (in), 29 (in), 30 (in), 31 (in), 32 (in)

## Header2
designator J?, comment Header 2pin 0.1"
Header, 0.1", 2-Pin straight (Any equivalent - may need to be value added); Manufacturer: Digikey; Manufacturers P/N: A26508-02-ND
footprint HDR1X2
pins: 1, 2

## Header6x2
designator J?, comment 6x2 header
footprint HDR2X6
pins: 1, 2, 3, 4, 5, 6, 7, 8, 9, 10, 11, 12

## Header18
designator J?
footprint HDR1X18
pins: 1, 2, 3, 4, 5, 6, 7, 8, 9, 10, 11, 12, 13, 14, 15, 16, 17, 18

## Header 2X2
designator J?, comment Header 2X2 0.1"
Header, 0.1" 2-Pin per row, Dual row (Any equivalent - may need to be value added); Manufacturer: Tyco Electronics; Manufacturers P/N: 4-103783-0-20 Broken Up
signal-integrity model Connector
footprint HDR2X2
pins: 1, 2, 3, 4

## Header 3
designator J?, comment Header 3pin 0.1"
Header, 0.1"  3-Pin straight (Any equivalent - may need to be value added); Manufacturer: Digikey; Manufacturers P/N: A26508-03-ND
footprint HDR1X3
signal-integrity model Connector
pins: 1, 2, 3

## Header 3X2
designator J?, comment Header 3X2 0.1"
Header, 0.1" 3-Pin per row, Dual row (Any equivalent - may need to be value added); Manufacturer: Tyco Electronics; Manufacturers P/N: 4-103783-0-20 Broken Up
footprint HDR2X3 (Connector; Header; 3x2 Position)
signal-integrity model Connector
pins: 1, 2, 3, 4, 5, 6

## Header 4
designator J?
Header, 0.1"  4-Pin straight
signal-integrity model Connector
footprint HDR1X4
pins: 1, 2, 3, 4

## Header 5X2
designator J?
Header, 0.1" 5-Pin, Dual row straight
footprint HDR2X5 (Connector; Header; 5x2 Position)
signal-integrity model Connector
pins: 1, 2, 3, 4, 5, 6, 7, 8, 9, 10

## Header 6
designator J?, comment Header 6pin 0.1"  Assembly: JTAG Expansion
Header, 0.1" 6-Pin straight (Any equivalent - may need to be value added); Manufacturer: Digikey; Manufacturers P/N: A26508-06-ND
footprint HDR1X6
signal-integrity model Connector
pins: 1, 2, 3, 4, 5, 6

## Header 6_1
designator J?, comment Header 6  Assembly: DNL, JTAG Expansion
Header, 0.1" 6-Pin straight
footprint HDR1X6 (Connector; Header; 6 Position)
signal-integrity model Connector
pins: 1, 2, 3, 4, 5, 6

## HFD3180-203
designator U?
VCSEL receiver
footprint HFD3180-203
footprint HFD3180-203(VerticalAdapt) (VCSEL receiver with vertical LC-TO adapter)
pins: 1 Vout+, 2 Vout-, 3 VPD, 4 VCC, 5 GND(Case)

## HFE4192-581
designator U?, comment VCSEL Transmitter
footprint HFE4192-581
pins: 1 VCSELCathode, 2 VCSELAnode, 3 MonitorCathode, 4 MonitorAnode(Case)

## HFJ11-1G01E
designator P?
Gigabit HALO RJ45
footprint HALO_RJ45
pins: 1, 2, 3, 4, 5, 6, 7, 8, 9 VCC, 10 GND, 11 GND (power), 12 GND (power)

## HFJ11-1G01E_1
designator P?, comment HFJ11-1G01E
Gigabit HALO RJ45
footprint HALO_RJ45 (Gigabit Network RJ45)
pins: 1, 2, 3, 4, 5, 6, 7, 8, 9 VCC, 10 GND, 11 GND (power), 12 GND (power)

## IL712
designator U?, comment Isolator 1/1
footprint DIP-8 (DIP; 8 Leads; Row Spacing 7.62 mm; Pitch 2.54 mm)
pins: 1 Vdd1, 2 In1, 3 Out2, 4 Gnd1, 5 Gnd2, 6 In2, 7 Out1, 8 Vdd2

## INA326
designator U?
footprint TSOP65P490X110-8N (TSOP, 8-Leads, Body 3.1x3.1mm (max), Pitch 0.65mm, IPC Medium Density)
pins: 1 R1, 2 Vin-, 3 Vin+, 4 V-, 5 R2, 6 Vo, 7 V+, 8 R1

## Inductor
designator L?, comment Ferrite bead
Inductor SM 0805; Manufacturer: TDK Corporation; Manufacturers P/N: MMZ2012R102A; Code_IEC: 1005
footprint INDC2012-0805
simulation model INDUCTOR (Inductor)
signal-integrity model Inductor
pins: 1, 2

## Inductor0
designator L?, comment 47uH, CBL2012T470M  Param: 5.46 Ohm, 0.1A, 0805
Inductor 47uH, 5.46 Ohm, 0.1A, 0805; Manufacturer: Taiyo Yuden
footprint 0805
pins: 1, 2

## Inductor1
designator L?, comment 68uH, SLF6028T-680MR50-PF  Param: 290.0 mOhm, 0.5A
Inductor 68uH, 290.0 mOhm, 0.5A; Manufacturer: TDK Corporation
footprint LL-6028Univ
pins: 1, 2

## Inductor1_1
designator L?, comment 10uH, SLF7045T-100M1R3-PF
Inductor 10uH, 50.0 mOhm, 1.3A; Manufacturer: TDK Corporation
footprint LL-6028Univ
pins: 1, 2

## Inductor2
designator L?, comment 2.7uH, PM12645S-2R7M
Inductor 7.3mOhms 15A 2.7uH; Manufacturer: JW Miller A Bourns Company
simulation model INDUCTOR (Inductor)
signal-integrity model Inductor
footprint LL-PM1265Univ
pins: 1, 2

## Inductor3
designator L?, comment 1.2 uH, MLC1255-122MLC
1.2uH Inductor, 2.38 mOhm, 20A; Manufacturer: Coilcraft
simulation model INDUCTOR (Inductor)
signal-integrity model Inductor
footprint LL-PM1265Univ
pins: 1, 2

## Inductor3A33uH
designator L?, comment 33uH, 3A  Footprint: SRR1208
Inductor, 33uH, 3A, 1208
footprint 1208
pins: 1, 2

## Inductor4
designator L?, comment 68uH, Wurth 7447789006  Param: 47mOhm, 2.5A
Inductor 68uH, 44mOhm, 2.5A
footprint WURTHIND7447789006 (Wurth 68uH Inductor)
pins: 1, 2

## Inductor_2
designator L?, comment Ferrite bead
Inductor SM 0805; Manufacturer: TDK Corporation; Manufacturers P/N: MMZ2012R102A; Code_IEC: 1005
footprint INDC2012-0805
simulation model INDUCTOR (Inductor)
signal-integrity model Inductor
pins: 1, 2

## Jumper
designator J?, comment SN7
Jumper Wire; Manufacturer: Make in house; Manufacturers P/N: None - cut piece of wire
footprint MHDR1X2
pins: 1 C1, 2 C2

## Jumper_1
designator J?, comment SN
Jumper Wire - Assembly house please short.
footprint RAD-0.2 (Jumper Wire; 2 Leads)
footprint MHDR1X2 (Connector; Header; 2 Position)
pins: 1 C1, 2 C2

## Jumper_100mil
designator J?, comment Header 2pin 0.1"
Header, 0.1", 2-Pin straight (Any equivalent - may need to be value added); Manufacturer: Digikey; Manufacturers P/N: A26508-02-ND
footprint HDR1X2
pins: 1, 2

## Jumper_100mil_1
designator J?, comment DNL Header 2
Header, 0.1" 2-Pin straight
footprint HDR1X2
pins: 1, 2

## LAT Attenuator Minicircuits
designator U?, comment Minicircuits LAT Attenuator
footprint PL-225 (Minicircuits 4 pin  SOT143)
pins: 1 Gnd, 2 Out, 3 Gnd, 4 In

## LC_TO_Adapter
designator J?, comment www.acronymeo.com - LCtoTO
FrontPanelLaserMount

## LCboard_FH16-90S-0.3SHW(05)
designator J?, comment ZIF Connector
footprint LCBoard_ZIFCon (HFP190CT-ND)
pins: 1, 2, 3, 4, 5, 6, 7, 8, 9, 10, 11, 12, 13, 14, 15, 16, 17, 18, 19, 20, 21, 22, 23, 24, 25, 26, 27, 28, 29, 30, 31, 32, 33, 34, 35, 36, 37, 38, 39, 40, 41, 42, 43, 44, 45, 46, 47, 48, 49, 50, 51, 52, 53, 54, 55, 56, 57, 58, 59, 60, 61, 62, 63, 64, 65, 66, 67, 68, 69, 70, 71, 72, 73, 74, 75, 76, 77, 78, 79, 80, 81, 82, 83, 84, 85, 86, 87, 88, 89, 90

## LCBoard_GlenairMicroDsub21
designator J?
LCBoard_GlenairMicroDsub21
signal-integrity model D Subminiature
footprint MicroD-MWDM2L-21SCBRP-.110 (Glenair MicroD 21 pin)
pins: 1, 2, 3, 4, 5, 6, 7, 8, 9, 10, 11, 12, 13, 14, 15, 16, 17, 18, 19, 20, 21, MH1, MH2

## LCboardInductor7
designator L?, comment 7 inductors
footprint LCboardInductor7
pins: 1, 2, 3, 4, 5, 6, 7, 8, 9, 10, 11, 12, 13, 14

## LCboardInductor8
designator L?, comment 8 inductors
footprint LCboardInductor8
pins: 1, 2, 3, 4, 5, 6, 7, 8, 9, 10, 11, 12, 13, 14, 15, 16

## LED
designator D?, comment LTST-S270KSKT, Yellow  (value not drawn)
LED Side View Yellow 0603; Manufacturer: Lite-On Inc
footprint LED-S270KGKT (Footprint not found)
pins: 1 A, 2 K

## LED3
designator D?, comment LED0805, GRN
LED 0805 LTST-C170GKT; Manufacturer: Lite-On Inc
footprint LED_LTST-C170GKT
simulation model LED3 (Diode)
pins: 1 A, 2 K

## LED3_1
designator D?, comment LED0805, GRN
LED 0805 LTST-C170GKT
footprint SMD _LED (SMT LED; 2 Leads)
simulation model LED3 (Diode)
pins: 1 A, 2 K

## LED10array
designator U
footprint LED10array
pins: 1, 2, 3, 4, 5, 6, 7, 8, 9, 10, 11, 12, 13, 14, 15, 16, 17, 18, 19, 20

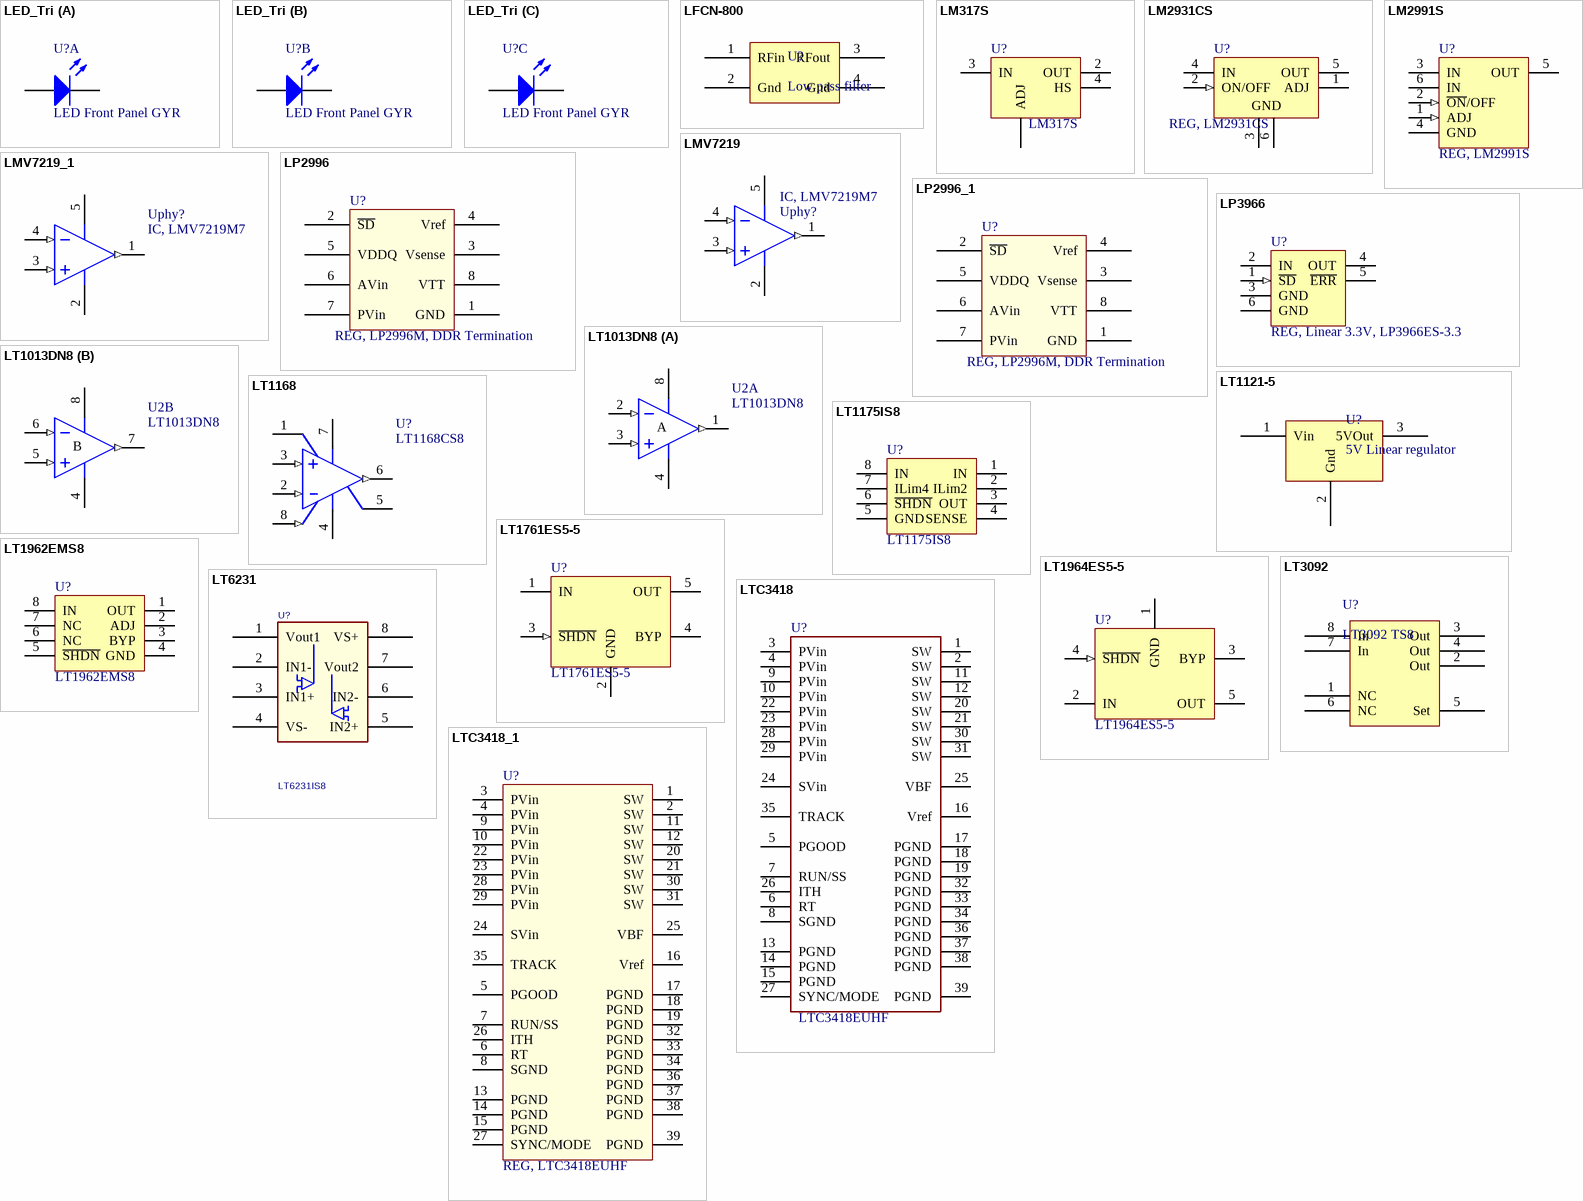
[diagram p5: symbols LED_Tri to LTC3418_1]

## LED_Tri
designator U?, comment LED Front Panel GYR
564-0200-132F
footprint LED_Tri_ (Three LEDs in one package)
part A pins: A1 A, K1 K
part B pins: A2 A, K2 K
part C pins: A3 A, K3 K

## LFCN-800
designator U?, comment Low pass filter
footprint FV1206
pins: 1 RFin, 2 Gnd, 3 RFout, 4 Gnd

## LM317S
designator U?
REG, POSITIVE ADJ TO-263; Manufacturer: National Semiconductor; Manufacturers P/N: LM317S/NOPB
footprint TO263-3
pins: 1 ADJ (power) "GND", 2 OUT (power), 3 IN (power), 4 HS (power) "Seating pin"

## LM2931CS
designator U?, comment REG, LM2931CS
Series Low-Dropout Regulator; Note: Tab is GND
footprint TS5B (D2-PAK; 5 Leads; Body 14.4 (inc. leads) x 10.4 mm (LxW max))
pins: 1 ADJ, 2 ON/OFF (in), 3 GND (power), 4 IN (power), 5 OUT (power), 6 GND (TAB) (power)

## LM2991S
designator U?, comment REG, LM2991S
Negative Low-Dropout Adjustable Regulator; Note: Tab is Input
footprint TS5B (D2-PAK; 5 Leads; Body 14.4 (inc. leads) x 10.4 mm (LxW max))
pins: 1 ADJ (in), 2 ~{ON}/OFF (in), 3 IN (power), 4 GND (power), 5 OUT (power), 6 IN (power)

## LMV7219
designator Uphy?, comment IC, LMV7219M7
Voltage Comparator; Manufacturer: National Semiconductor; Manufacturers P/N: LMV7219M7/NOPB
footprint MAA05A (SOT-353/SC-88A; 5 Leads; Body 2.1 x 2.4 mm, inc. leads (LxW max))
pins: 1 OUT (out), 2 V- (power), 3 IN+ (in), 4 IN- (in), 5 V+ (power)

## LMV7219_1
designator Uphy?, comment IC, LMV7219M7
Voltage Comparator
footprint MAA05A (SOT-353/SC-88A; 5 Leads; Body 2.1 x 2.4 mm, inc. leads (LxW max))
pins: 1 OUT (out), 2 V- (power), 3 IN+ (in), 4 IN- (in), 5 V+ (power)

## LP2996
designator U?, comment REG, LP2996M, DDR Termination
DDR Termination Regulator; Manufacturer: National Semiconductor; Manufacturers P/N: LP2996M/NOPB
footprint SO8
pins: 1 GND (power), 2 ~{SD}, 3 Vsense, 4 Vref, 5 VDDQ, 6 AVin, 7 PVin, 8 VTT

## LP2996_1
designator U?, comment REG, LP2996M, DDR Termination
DDR Termination Regulator
footprint M08A (Small Outline; 8 Leads; Body Width 3.9 mm; Pitch 1.27 mm)
pins: 1 GND (power), 2 ~{SD}, 3 Vsense, 4 Vref, 5 VDDQ, 6 AVin, 7 PVin, 8 VTT

## LP3966
designator U?, comment REG, Linear 3.3V, LP3966ES-3.3
3A Fast Ultra Low Dropout Linear Regulator
footprint TS5B (D2-PAK; 5 Leads; Body 14.4 (inc. leads) x 10.4 mm (LxW max))
pins: 1 ~{SD} (in), 2 IN (power), 3 GND (power), 4 OUT (power), 5 ~{ERR}, 6 GND (power)

## LT1013DN8
designator U2
Dual Precision Operational Amplifier; Note: 206
footprint N8 (DIP, 8-Leads, Row Spacing 7.62mm, Pitch 2.54mm, Body 9.78x6.48mm)
3D model N8 (DIP, Plastic, 8-Pin, Row Spacing 7.62 mm, Pitch 2.54 mm)
simulation model LT1013D (SUBCKT)
pins on every part: 4 V- (power), 8 V+ (power)
part A pins: 1 OUT (out), 2 IN- (in), 3 IN+ (in)
part B pins: 5 IN+ (in), 6 IN- (in), 7 OUT (out)

## LT1121-5
designator U?, comment 5V Linear regulator
footprint TO-92 (TO, Flat Index; 3 In-Line, Axial Leads; Body Dia. 5.1mm; Leads 0.48 x 0.48 mm (max))
pins: 1 Vin, 2 Gnd, 3 5VOut

## LT1168
designator U?, comment LT1168CS8
Amp, Instrumentation, Low bias current; Manufacturer: Linear Technology; Manufacturers P/N: LT1168CS8#PBF
simulation model LT1168 (Model Description)
footprint SO8
pins: 1 Rg1, 2 IN- (in), 3 IN+ (in), 4 V- (power), 5 REF, 6 OUT (out), 7 V+ (power), 8 Rg2 (in)

## LT1175IS8
designator U?
REG, negative micropower low dropout; Manufacturer: Linear Technology; Manufacturers P/N: LT1175IS8#PBF
footprint SO8
pins: 1 IN (power), 2 ILim2, 3 OUT, 4 SENSE (power), 5 GND, 6 ~{SHDN}, 7 ILim4, 8 IN (power)

## LT1761ES5-5
designator U?
200mA, Low Noise, Low Dropout Positive Micropower Regulator; Note: 1917
footprint S5_N (SOT23, 5-Leads, Body 3x1.6mm, Pitch 0.95mm, Lead Span 2.8mm, IPC Medium Density)
footprint S5_L (SOT23, 5-Leads, Body 3x1.6mm, Pitch 0.95mm, Lead Span 2.8mm, IPC High Density)
footprint S5_M (SOT23, 5-Leads, Body 3x1.6mm, Pitch 0.95mm, Lead Span 2.8mm, IPC Low Density)
pins: 1 IN (power), 2 GND (power), 3 ~{SHDN} (in), 4 BYP, 5 OUT (power)

## LT1962EMS8
designator U?
REG, micropower, low noise, low  dropout; Manufacturer: Linear Technology; Manufacturers P/N: LT1962EMS8#PBF
footprint MSOP-8
pins: 1 OUT (power), 2 ADJ, 3 BYP, 4 GND (power), 5 ~{SHDN}, 6 NC, 7 NC, 8 IN (power)

## LT1964ES5-5
designator U?
200mA, Low Noise, Low Dropout Negative Micropower Regulator; Note: 1917
footprint S5_N (SOT23, 5-Leads, Body 3x1.6mm, Pitch 0.95mm, Lead Span 2.8mm, IPC Medium Density)
footprint S5_L (SOT23, 5-Leads, Body 3x1.6mm, Pitch 0.95mm, Lead Span 2.8mm, IPC High Density)
footprint S5_M (SOT23, 5-Leads, Body 3x1.6mm, Pitch 0.95mm, Lead Span 2.8mm, IPC Low Density)
pins: 1 GND (power), 2 IN (power), 3 BYP, 4 ~{SHDN} (in), 5 OUT (power)

## LT3092
designator U?, comment LT3092 TS8
footprint SOT23-8 (SSOP; 8 Leads; Body Width 1.6 mm; Pitch 0.65 mm)
pins: 1 NC, 2 Out, 3 Out, 4 Out, 5 Set, 6 NC, 7 In, 8 In

## LT6231
designator U?, comment LT6231IS8
COMPFIXED: NO; COMPGROUP: 0; COMPHEIGHT: 0.000; COMPROT: 180; COMPSIDE: TOP
footprint SO8/L200
footprint SO8/L200
pins: 1 Vout1, 2 IN1-, 3 IN1+, 4 VS-, 5 IN2+, 6 IN2-, 7 Vout2, 8 VS+

## LTC3418
designator U?, comment LTC3418EUHF
REG, 8A, 4MHz, Monolithic Syncronous Step-Down; Manufacturer: Linear Technology; Manufacturers P/N: LTC3418EUHF#PBF
footprint QFN38(5X7)
pins: 1 SW, 2 SW, 3 PVin (power), 4 PVin (power), 5 PGOOD, 6 RT, 7 RUN/SS, 8 SGND (power), 9 PVin (power), 10 PVin (power), 11 SW, 12 SW, 13 PGND (power), 14 PGND (power), 15 PGND (power), 16 Vref, 17 PGND (power), 18 PGND (power), 19 PGND (power), 20 SW, 21 SW, 22 PVin (power), 23 PVin (power), 24 SVin, 25 VBF, 26 ITH, 27 SYNC/MODE, 28 PVin (power), 29 PVin (power), 30 SW, 31 SW, 32 PGND (power), 33 PGND (power), 34 PGND (power), 35 TRACK, 36 PGND (power), 37 PGND (power), 38 PGND (power), 39 PGND (power)

## LTC3418_1
designator U?, comment REG, LTC3418EUHF
8A, 4MHz, Monolithic Syncronous Step-Down Regulator
footprint UH38_N (38-Lead Plastic QFN)
pins: 1 SW, 2 SW, 3 PVin (power), 4 PVin (power), 5 PGOOD, 6 RT, 7 RUN/SS, 8 SGND (power), 9 PVin (power), 10 PVin (power), 11 SW, 12 SW, 13 PGND (power), 14 PGND (power), 15 PGND (power), 16 Vref, 17 PGND (power), 18 PGND (power), 19 PGND (power), 20 SW, 21 SW, 22 PVin (power), 23 PVin (power), 24 SVin, 25 VBF, 26 ITH, 27 SYNC/MODE, 28 PVin (power), 29 PVin (power), 30 SW, 31 SW, 32 PGND (power), 33 PGND (power), 34 PGND (power), 35 TRACK, 36 PGND (power), 37 PGND (power), 38 PGND (power), 39 PGND (power)

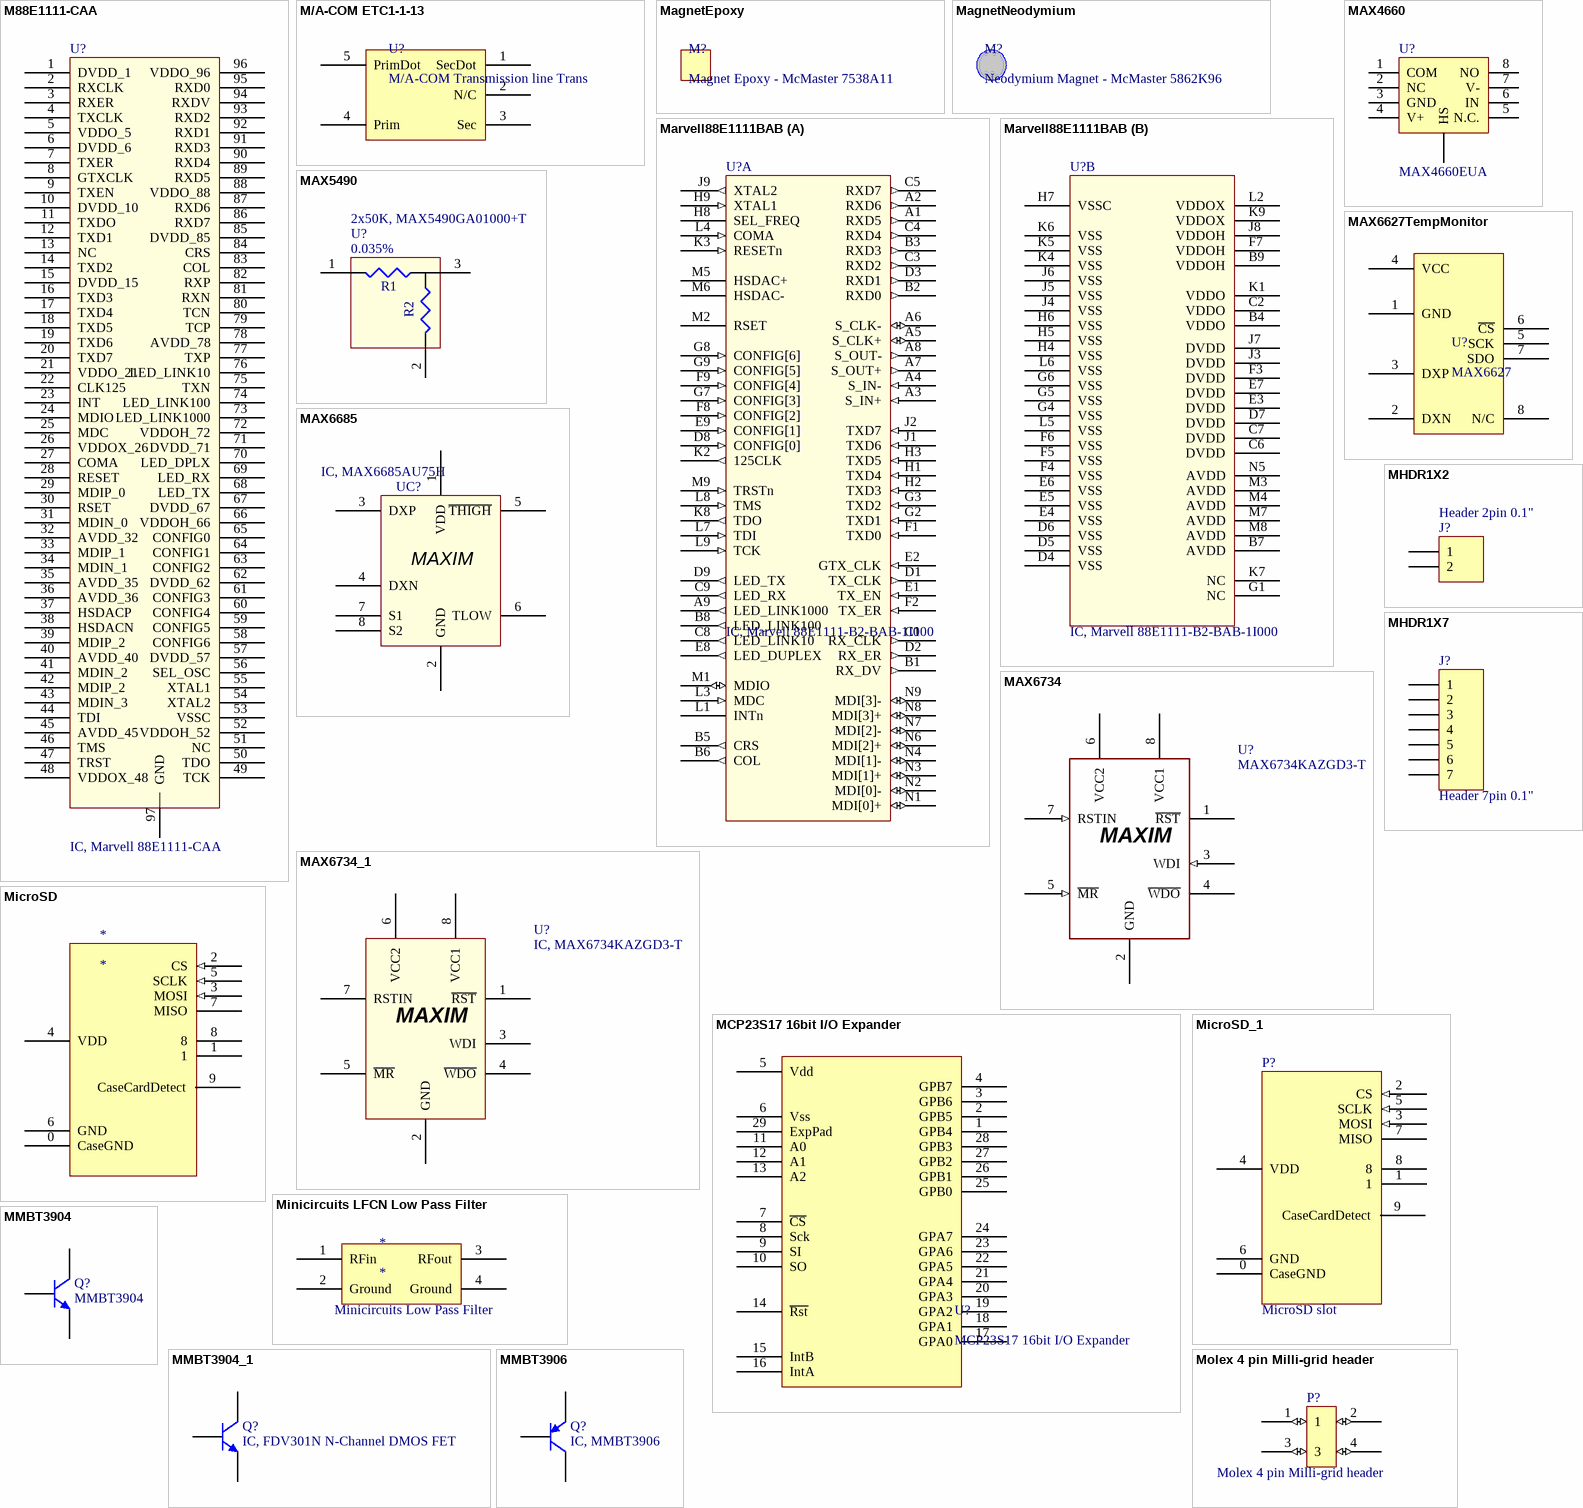
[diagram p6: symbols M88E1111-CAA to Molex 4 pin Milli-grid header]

## M88E1111-CAA
designator U?, comment IC, Marvell 88E1111-CAA
PHY 10/100/1000 Alaska Single-Port Gigabit Transceiver
footprint BCC_96 (96-lead Bump Chip Carrier)
pins: 1 DVDD_1, 2 RXCLK, 3 RXER, 4 TXCLK, 5 VDDO_5, 6 DVDD_6, 7 TXER, 8 GTXCLK, 9 TXEN, 10 DVDD_10, 11 TXDO, 12 TXD1, 13 NC, 14 TXD2, 15 DVDD_15, 16 TXD3, 17 TXD4, 18 TXD5, 19 TXD6, 20 TXD7, 21 VDDO_21, 22 CLK125, 23 INT, 24 MDIO, 25 MDC, 26 VDDOX_26, 27 COMA, 28 RESET, 29 MDIP_0, 30 RSET, 31 MDIN_0, 32 AVDD_32, 33 MDIP_1, 34 MDIN_1, 35 AVDD_35, 36 AVDD_36, 37 HSDACP, 38 HSDACN, 39 MDIP_2, 40 AVDD_40, 41 MDIN_2, 42 MDIP_2, 43 MDIN_3, 44 TDI, 45 AVDD_45, 46 TMS, 47 TRST, 48 VDDOX_48, 49 TCK, 50 TDO, 51 NC, 52 VDDOH_52, 53 VSSC, 54 XTAL2, 55 XTAL1, 56 SEL_OSC, 57 DVDD_57, 58 CONFIG6, 59 CONFIG5, 60 CONFIG4, 61 CONFIG3, 62 DVDD_62, 63 CONFIG2, 64 CONFIG1, 65 CONFIG0, 66 VDDOH_66, 67 DVDD_67, 68 LED_TX, 69 LED_RX, 70 LED_DPLX, 71 DVDD_71, 72 VDDOH_72, 73 LED_LINK1000, 74 LED_LINK100, 75 TXN, 76 LED_LINK10, 77 TXP, 78 AVDD_78, 79 TCP, 80 TCN, 81 RXN, 82 RXP, 83 COL, 84 CRS, 85 DVDD_85, 86 RXD7, 87 RXD6, 88 VDDO_88, 89 RXD5, 90 RXD4, 91 RXD3, 92 RXD1, 93 RXD2, 94 RXDV, 95 RXD0, 96 VDDO_96, 97 GND

## M/A-COM ETC1-1-13
designator U?, comment M/A-COM Transmission line Trans
footprint M/A-COM ETC1-1-13 (RF 1:1: transformer)
pins: 1 SecDot, 2 N/C, 3 Sec, 4 Prim, 5 PrimDot

## MagnetEpoxy
designator M?, comment Magnet Epoxy - McMaster 7538A11
Magnet Epoxy

## MagnetNeodymium
designator M?, comment Neodymium Magnet - McMaster 5862K96
Neodymium Magnet

## Marvell88E1111BAB
designator U?, comment IC, Marvell 88E1111-B2-BAB-1I000
PHY 10/100/1000 Alaska Single-Port Gigabit Transceiver
footprint BGA117C100P13X9_1400X1000X154 (BGA, 117-Leads, Body 14.0x10.0mm,  Pitch 1.00mm)
part A pins: A1 RXD5 (out), A2 RXD6 (out), A3 S_IN+ (in), A4 S_IN- (in), A5 S_CLK+ (io), A6 S_CLK- (io), A7 S_OUT+ (out), A8 S_OUT- (out), A9 LED_LINK1000 (out), B1 RX_DV (out), B2 RXD0 (out), B3 RXD3 (out), B5 CRS (out), B6 COL (out), B8 LED_LINK100 (out), C1 RX_CLK (out), C3 RXD2 (out), C4 RXD4 (out), C5 RXD7 (out), C8 LED_LINK10 (out), C9 LED_RX (out), D1 TX_CLK (out), D2 RX_ER (out), D3 RXD1 (out), D8 CONFIG[0] (in), D9 LED_TX (out), E1 TX_EN (in), E2 GTX_CLK (in), E8 LED_DUPLEX (out), E9 CONFIG[1] (in), F1 TXD0 (in), F2 TX_ER (in), F8 CONFIG[2] (in), F9 CONFIG[4] (in), G2 TXD1 (in), G3 TXD2 (in), G7 CONFIG[3] (in), G8 CONFIG[6] (in), G9 CONFIG[5] (in), H1 TXD4 (in), H2 TXD3 (in), H3 TXD5 (in), H8 SEL_FREQ, H9 XTAL1 (in), J1 TXD6 (in), J2 TXD7 (in), J9 XTAL2 (out), K2 125CLK (out), K3 RESETn (in), K8 TDO (out), L1 INTn (oc), L3 MDC (in), L4 COMA (in), L7 TDI (in), L8 TMS (in), L9 TCK (in), M1 MDIO (io), M2 RSET, M5 HSDAC+, M6 HSDAC-, M9 TRSTn (in), N1 MDI[0]+ (io), N2 MDI[0]- (io), N3 MDI[1]+ (io), N4 MDI[1]- (io), N6 MDI[2]+ (io), N7 MDI[2]- (io), N8 MDI[3]+ (io), N9 MDI[3]- (io)
part B pins: B4 VDDO, B7 AVDD, B9 VDDOH, C2 VDDO, C6 DVDD, C7 DVDD, D4 VSS (power), D5 VSS (power), D6 VSS (power), D7 DVDD, E3 DVDD, E4 VSS (power), E5 VSS (power), E6 VSS (power), E7 DVDD, F3 DVDD, F4 VSS (power), F5 VSS (power), F6 VSS (power), F7 VDDOH, G1 NC (hiz), G4 VSS (power), G5 VSS (power), G6 VSS (power), H4 VSS (power), H5 VSS (power), H6 VSS (power), H7 VSSC (power), J3 DVDD, J4 VSS (power), J5 VSS (power), J6 VSS (power), J7 DVDD, J8 VDDOH, K1 VDDO, K4 VSS (power), K5 VSS (power), K6 VSS (power), K7 NC (hiz), K9 VDDOX (power), L2 VDDOX (power), L5 VSS (power), L6 VSS (power), M3 AVDD (power), M4 AVDD (power), M7 AVDD (power), M8 AVDD (power), N5 AVDD (power)

## MAX4660
designator U?, comment MAX4660EUA
Analog Switch, 150mA, 25 Ohm (38 Ohm); Manufacturer: Maxim Integrated Products
footprint MSOP8-EP
pins: 1 COM, 2 NC, 3 GND (power), 4 V+ (power), 5 N.C., 6 IN, 7 V- (power), 8 NO, 9 HS (power) "GND"

## MAX5490
designator U?, comment 2x50K, MAX5490GA01000+T  Param: 0.035%
100k Precision-Matched Resistor-Divider 0.035%; Manufacturer: Maxim Integrated Products; Manufacturers P/N: MAX5490GA01000+T-ND
footprint SOT23
pins: 1 P1, 2 P2, 3 P3

## MAX6627TempMonitor
designator U?, comment MAX6627
Temperature Monitor
footprint SOT23-8 (SSOP; 8 Leads; Body Width 1.6 mm; Pitch 0.65 mm)
pins: 1 GND, 2 DXN, 3 DXP, 4 VCC, 5 SCK, 6 ~{CS}, 7 SDO, 8 N/C

## MAX6685
designator UC?, comment IC, MAX6685AU75H
Dual-Output Remote-Junction Temperature Switch
footprint UMAX8 (Shrink Small Outline; 8 Leads; Body Width 3 mm; Pitch 0.65 mm)
footprint uSOP8
pins: 1 VDD (power), 2 GND (power), 3 DXP, 4 DXN, 5 ~{THIGH}, 6 TLOW, 7 S1, 8 S2

## MAX6734
designator U?, comment MAX6734KAZGD3-T
Watchdog, uP Supervisory Circuit; Manufacturer: Maxim Integrated Products
footprint SOT23-8
pins: 1 ~{RST} (oc), 2 GND (power), 3 WDI (in), 4 ~{WDO} (oc), 5 ~{MR} (in), 6 VCC2 (power), 7 RSTIN (in), 8 VCC1 (power)

## MAX6734_1
designator U?, comment IC, MAX6734KAZGD3-T
uP Supervisory Circuit
footprint SOP23-8
pins: 1 ~{RST}, 2 GND (power), 3 WDI, 4 ~{WDO}, 5 ~{MR}, 6 VCC2 (power), 7 RSTIN, 8 VCC1 (power)

## MCP23S17 16bit I/O Expander
designator U?
footprint QFN65P600X600X100-28M (QFN, 28-Leads, Body 6.0x6.0mm (max), Pitch 0.65mm, IPC Low Density)
pins: 1 GPB4, 2 GPB5, 3 GPB6, 4 GPB7, 5 Vdd, 6 Vss, 7 ~{CS}, 8 Sck, 9 SI, 10 SO, 11 A0, 12 A1, 13 A2, 14 ~{Rst}, 15 IntB, 16 IntA, 17 GPA0, 18 GPA1, 19 GPA2, 20 GPA3, 21 GPA4, 22 GPA5, 23 GPA6, 24 GPA7, 25 GPB0, 26 GPB1, 27 GPB2, 28 GPB3, 29 ExpPad

## MHDR1X2
designator J?, comment Header 2pin 0.1"
Header, 2-Pin; Manufacturer: Digikey; Manufacturers P/N: A26508-02-ND
footprint MHDR1X2
signal-integrity model Connector
pins: 1, 2

## MHDR1X7
designator J?, comment Header 7pin 0.1"
Header, 7-Pin (Any equivalent - may need to be value added); Manufacturer: Digikey; Manufacturers P/N: A26508-07-ND
footprint MHDR1X7 (Connector; Header; 7 Position)
signal-integrity model Connector
pins: 1, 2, 3, 4, 5, 6, 7

## MicroSD
designator *
footprint MicroSD (MicroSD card from Multicomp (TFCMF-20815B0T0))
pins: 0 CaseGND, 1, 2 CS (in), 3 MOSI (in), 4 VDD, 5 SCLK (in), 6 GND, 7 MISO (oc), 8, 9 CaseCardDetect

## MicroSD_1
designator P?, comment MicroSD slot
Manufacturer: Multicomp; Manufacturers P/N: TFCMF-20815B0T0  (Newark:74M4846 P/N MC34929)
footprint 3M2900_MICROSD
pins: 0 CaseGND, 1, 2 CS (in), 3 MOSI (in), 4 VDD, 5 SCLK (in), 6 GND, 7 MISO (oc), 8, 9 CaseCardDetect

## Minicircuits LFCN Low Pass Filter
designator *
pins: 1 RFin, 2 Ground, 3 RFout, 4 Ground

## MMBT3904
designator Q?
Transistor, NPN Switching; Manufacturer: Fairchild Semiconductor
signal-integrity model MMBT3904
footprint SOT23
pins: 1 B, 2 E, 3 C

## MMBT3904_1
designator Q?, comment IC, FDV301N N-Channel DMOS FET
NPN Switching Transistor
simulation model QMMBT3904 (NPN)
signal-integrity model MMBT3904
footprint SOT23 (SOT-23; 3 Leads; Body 3.0 x 2.5 mm, inc. leads (LxW max))
pins: 1 B, 2 E, 3 C

## MMBT3906
designator Q?, comment IC, MMBT3906
PNP Switching Transistor
footprint SOT23 (SOT-23; 3 Leads; Body 3.0 x 2.5 mm, inc. leads (LxW max))
simulation model QMMBT3906 (PNP)
signal-integrity model MMBT3906
pins: 1 B, 2 E, 3 C

## Molex 4 pin Milli-grid header
designator P?
footprint Molex 4 pin Milli-grid header (Footprint not found)
pins: 1 (io), 2 (io), 3 (io), 4 (io)

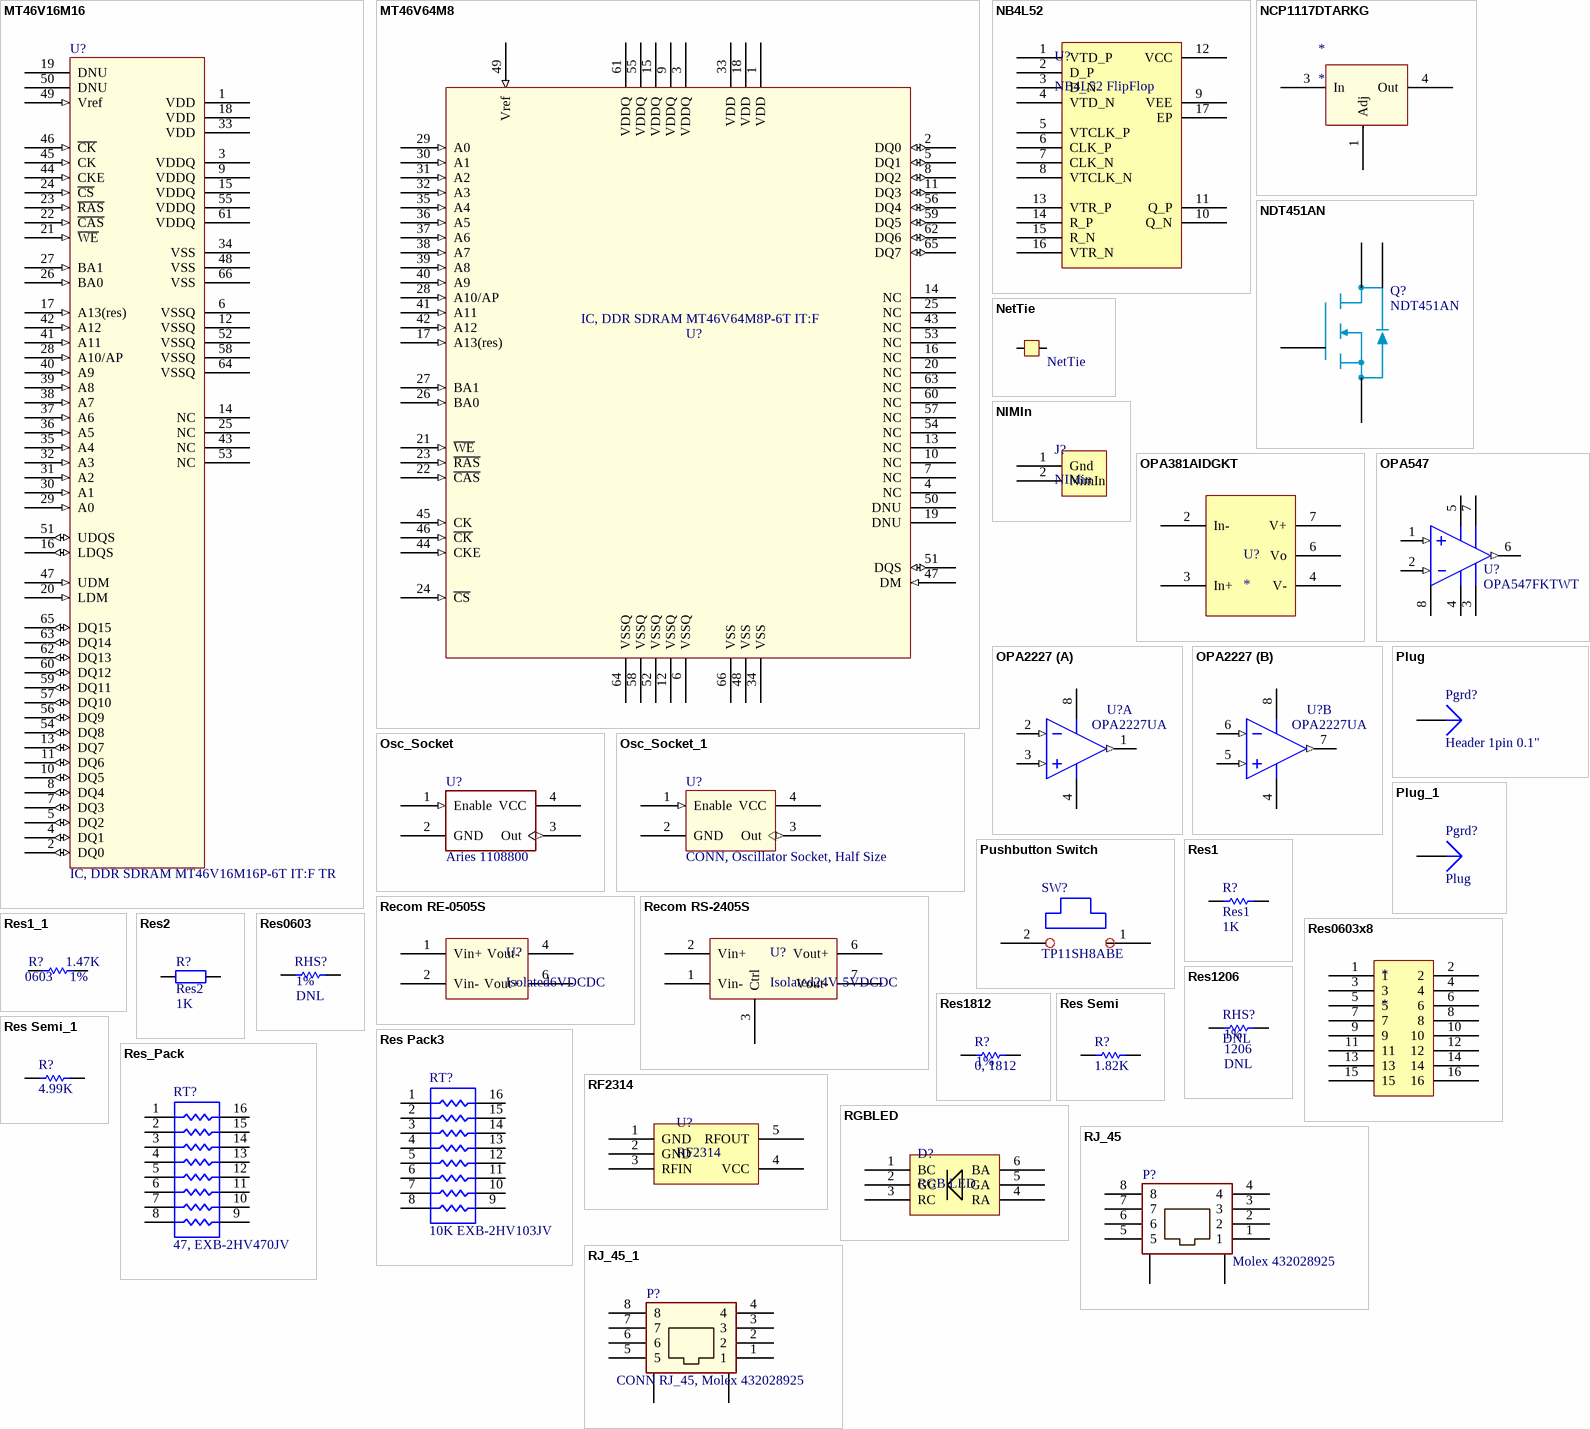
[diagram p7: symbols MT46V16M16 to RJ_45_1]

## MT46V16M16
designator U?, comment IC, DDR SDRAM MT46V16M16P-6T IT:F TR
256Mb, 4Meg X 16 X 4 banks DDR SDRAM
footprint TSOP-66
pins: 1 VDD (power), 2 DQ0 (io), 3 VDDQ (power), 4 DQ1 (io), 5 DQ2 (io), 6 VSSQ (power), 7 DQ3 (io), 8 DQ4 (io), 9 VDDQ (power), 10 DQ5 (io), 11 DQ6 (io), 12 VSSQ (power), 13 DQ7 (io), 14 NC, 15 VDDQ (power), 16 LDQS (io), 17 A13(res) (in), 18 VDD (power), 19 DNU, 20 LDM (in), 21 ~{WE} (in), 22 ~{CAS} (in), 23 ~{RAS} (in), 24 ~{CS} (in), 25 NC, 26 BA0 (in), 27 BA1 (in), 28 A10/AP (in), 29 A0 (in), 30 A1 (in), 31 A2 (in), 32 A3 (in), 33 VDD (power), 34 VSS (power), 35 A4 (in), 36 A5 (in), 37 A6 (in), 38 A7 (in), 39 A8 (in), 40 A9 (in), 41 A11 (in), 42 A12 (in), 43 NC, 44 CKE (in), 45 CK (in), 46 ~{CK} (in), 47 UDM (in), 48 VSS (power), 49 Vref (in), 50 DNU, 51 UDQS (io), 52 VSSQ (power), 53 NC, 54 DQ8 (io), 55 VDDQ (power), 56 DQ9 (io), 57 DQ10 (io), 58 VSSQ (power), 59 DQ11 (io), 60 DQ12 (io), 61 VDDQ (power), 62 DQ13 (io), 63 DQ14 (io), 64 VSSQ (power), 65 DQ15 (io), 66 VSS (power)

## MT46V64M8
designator U?, comment IC, DDR SDRAM MT46V64M8P-6T IT:F
512 Mb, 16Meg X 8 X 4 banks DDR SDRAM; Manufacturer: Micron Technology
footprint TSOP-66
pins: 1 VDD (power), 2 DQ0 (io), 3 VDDQ (power), 4 NC, 5 DQ1 (io), 6 VSSQ (power), 7 NC, 8 DQ2 (io), 9 VDDQ (power), 10 NC, 11 DQ3 (io), 12 VSSQ (power), 13 NC, 14 NC, 15 VDDQ (power), 16 NC, 17 A13(res) (in), 18 VDD (power), 19 DNU, 20 NC, 21 ~{WE} (in), 22 ~{CAS} (in), 23 ~{RAS} (in), 24 ~{CS} (in), 25 NC, 26 BA0 (in), 27 BA1 (in), 28 A10/AP (in), 29 A0 (in), 30 A1 (in), 31 A2 (in), 32 A3 (in), 33 VDD (power), 34 VSS (power), 35 A4 (in), 36 A5 (in), 37 A6 (in), 38 A7 (in), 39 A8 (in), 40 A9 (in), 41 A11 (in), 42 A12 (in), 43 NC, 44 CKE (in), 45 CK (in), 46 ~{CK} (in), 47 DM (in), 48 VSS (power), 49 Vref (in), 50 DNU, 51 DQS (io), 52 VSSQ (power), 53 NC, 54 NC, 55 VDDQ (power), 56 DQ4 (io), 57 NC, 58 VSSQ (power), 59 DQ5 (io), 60 NC, 61 VDDQ (power), 62 DQ6 (io), 63 NC, 64 VSSQ (power), 65 DQ7 (io), 66 VSS (power)

## NB4L52
designator U?, comment NB4L52 FlipFlop
FlipFlop fully differential GHz
footprint QFN50P325X325X100-16N (QFN, 16-Leads, Body 3.3x3.3mm (max), Pitch 0.50mm, IPC Medium Density)
pins: 1 VTD_P, 2 D_P, 3 D_N, 4 VTD_N, 5 VTCLK_P, 6 CLK_P, 7 CLK_N, 8 VTCLK_N, 9 VEE, 10 Q_N, 11 Q_P, 12 VCC, 13 VTR_P, 14 R_P, 15 R_N, 16 VTR_N, 17 EP

## NCP1117DTARKG
designator *
footprint TO-263 (D2-PAK/TO-263-AB; 3 Leads (1 Cropped); Body 15.9 (inc. leads) x 10.4 mm (LxW max))
pins: 1 Adj, 3 In, 4 Out

## NDT451AN
designator Q?
N type Mosfet  - 7.3A, 30V
footprint sot223
pins: 1 G, 2 D, 3 S, 4 Tab

## NetTie
designator NT?  (net tie, no BOM)
footprint NetTie
pins: 0, 1

## NIMIn
designator J?, comment NIMin
footprint NIMin
pins: 1 Gnd, 2 NimIn

## OPA381AIDGKT
designator U?
OPA381
footprint TSOP65P490X110-8N (TSOP, 8-Leads, Body 3.1x3.1mm (max), Pitch 0.65mm, IPC Medium Density)
pins: 1 N/C hidden, 2 In-, 3 In+, 4 V-, 5 N/C hidden, 6 Vo, 7 V+, 8 N/C hidden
